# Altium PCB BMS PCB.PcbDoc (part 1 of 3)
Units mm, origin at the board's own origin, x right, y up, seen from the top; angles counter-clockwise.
Board outline 105 x 42 mm, 6 copper layers (TOP, GND TOP, IN, GND IN, GND BOT, BOT), stack 1.517 mm thick; 241 components, 153 nets, 670 pads, 889 vias.
Unrouted connection lines stored in the file: 76.
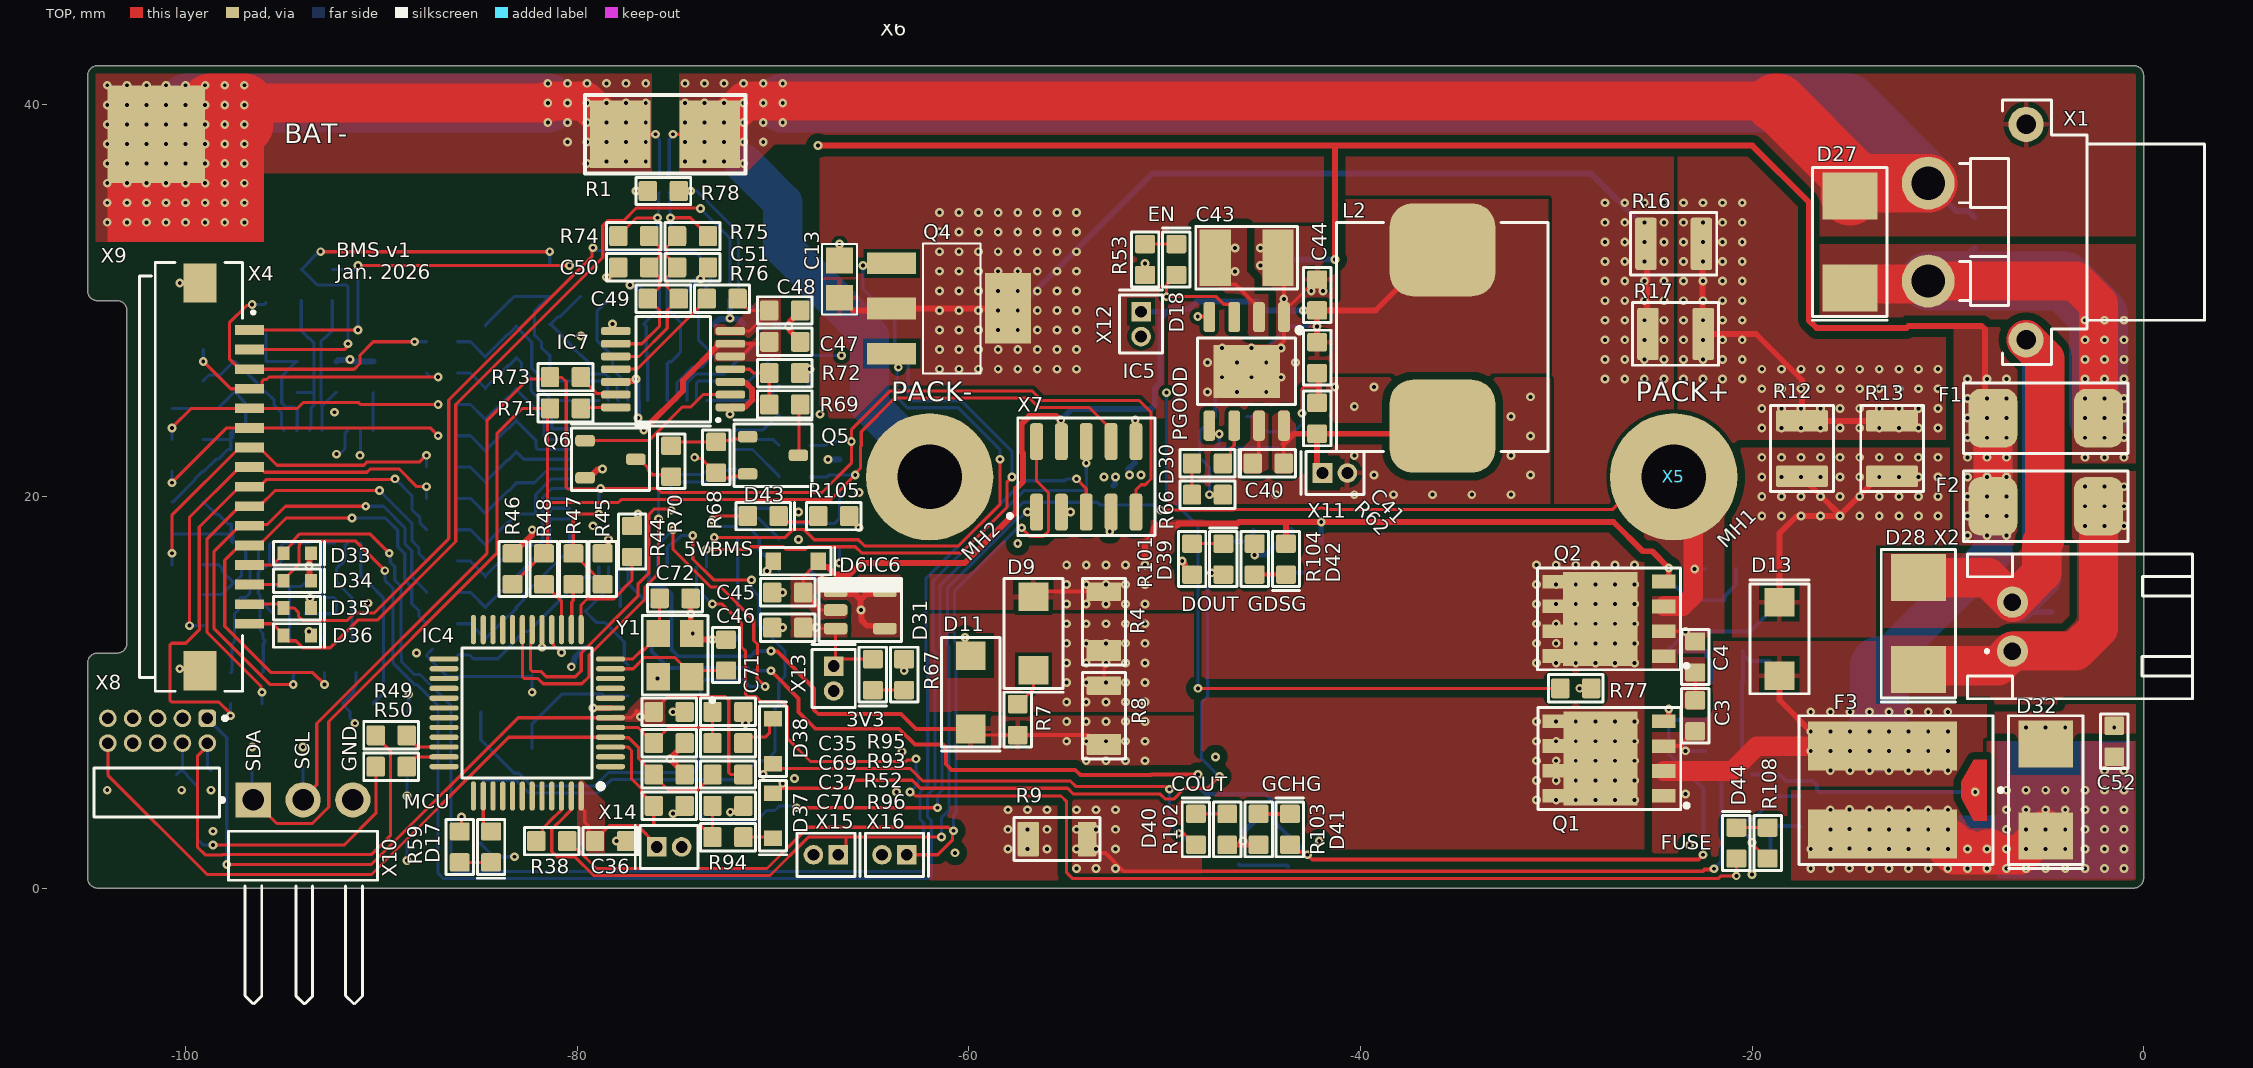
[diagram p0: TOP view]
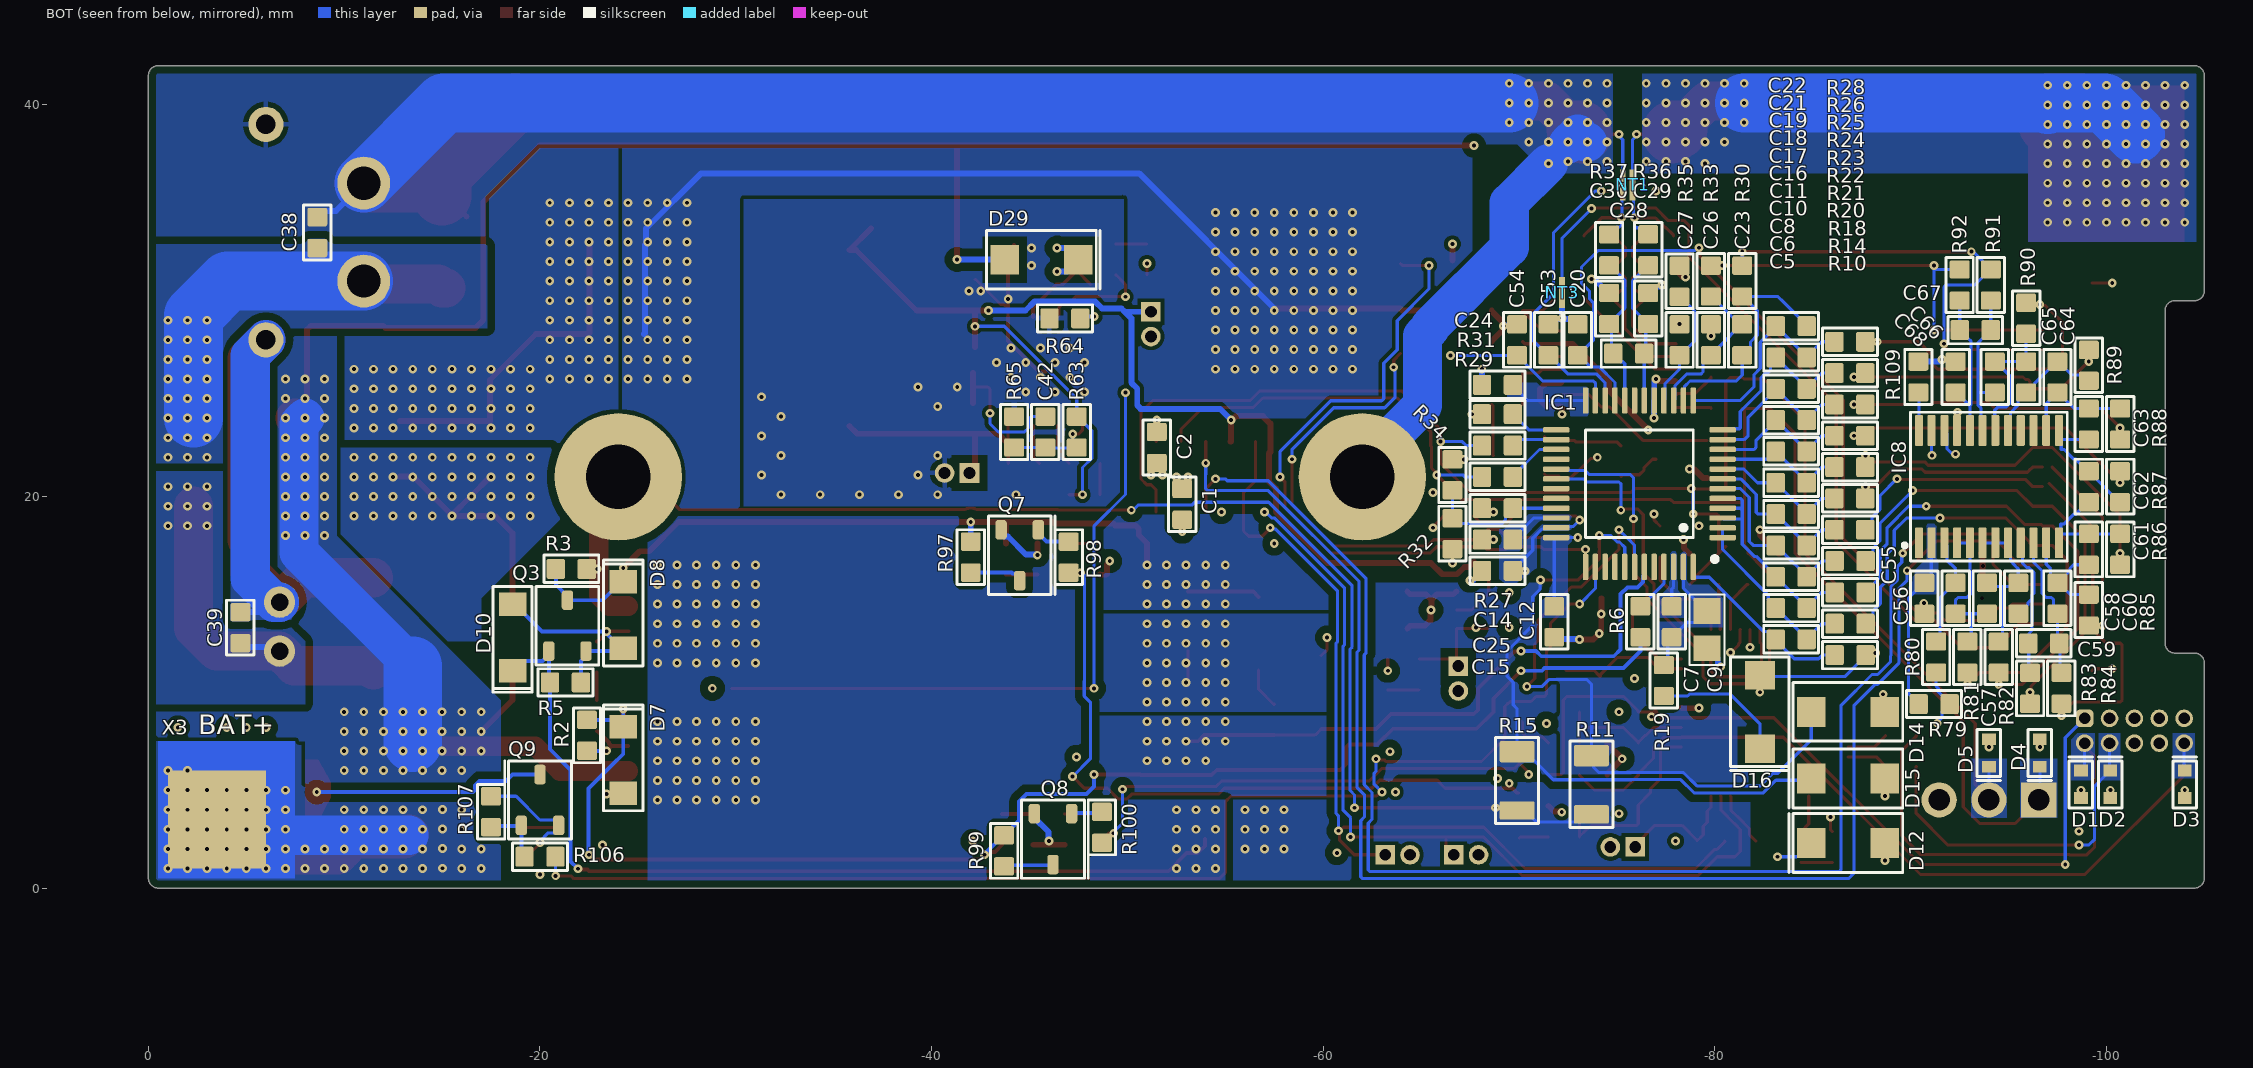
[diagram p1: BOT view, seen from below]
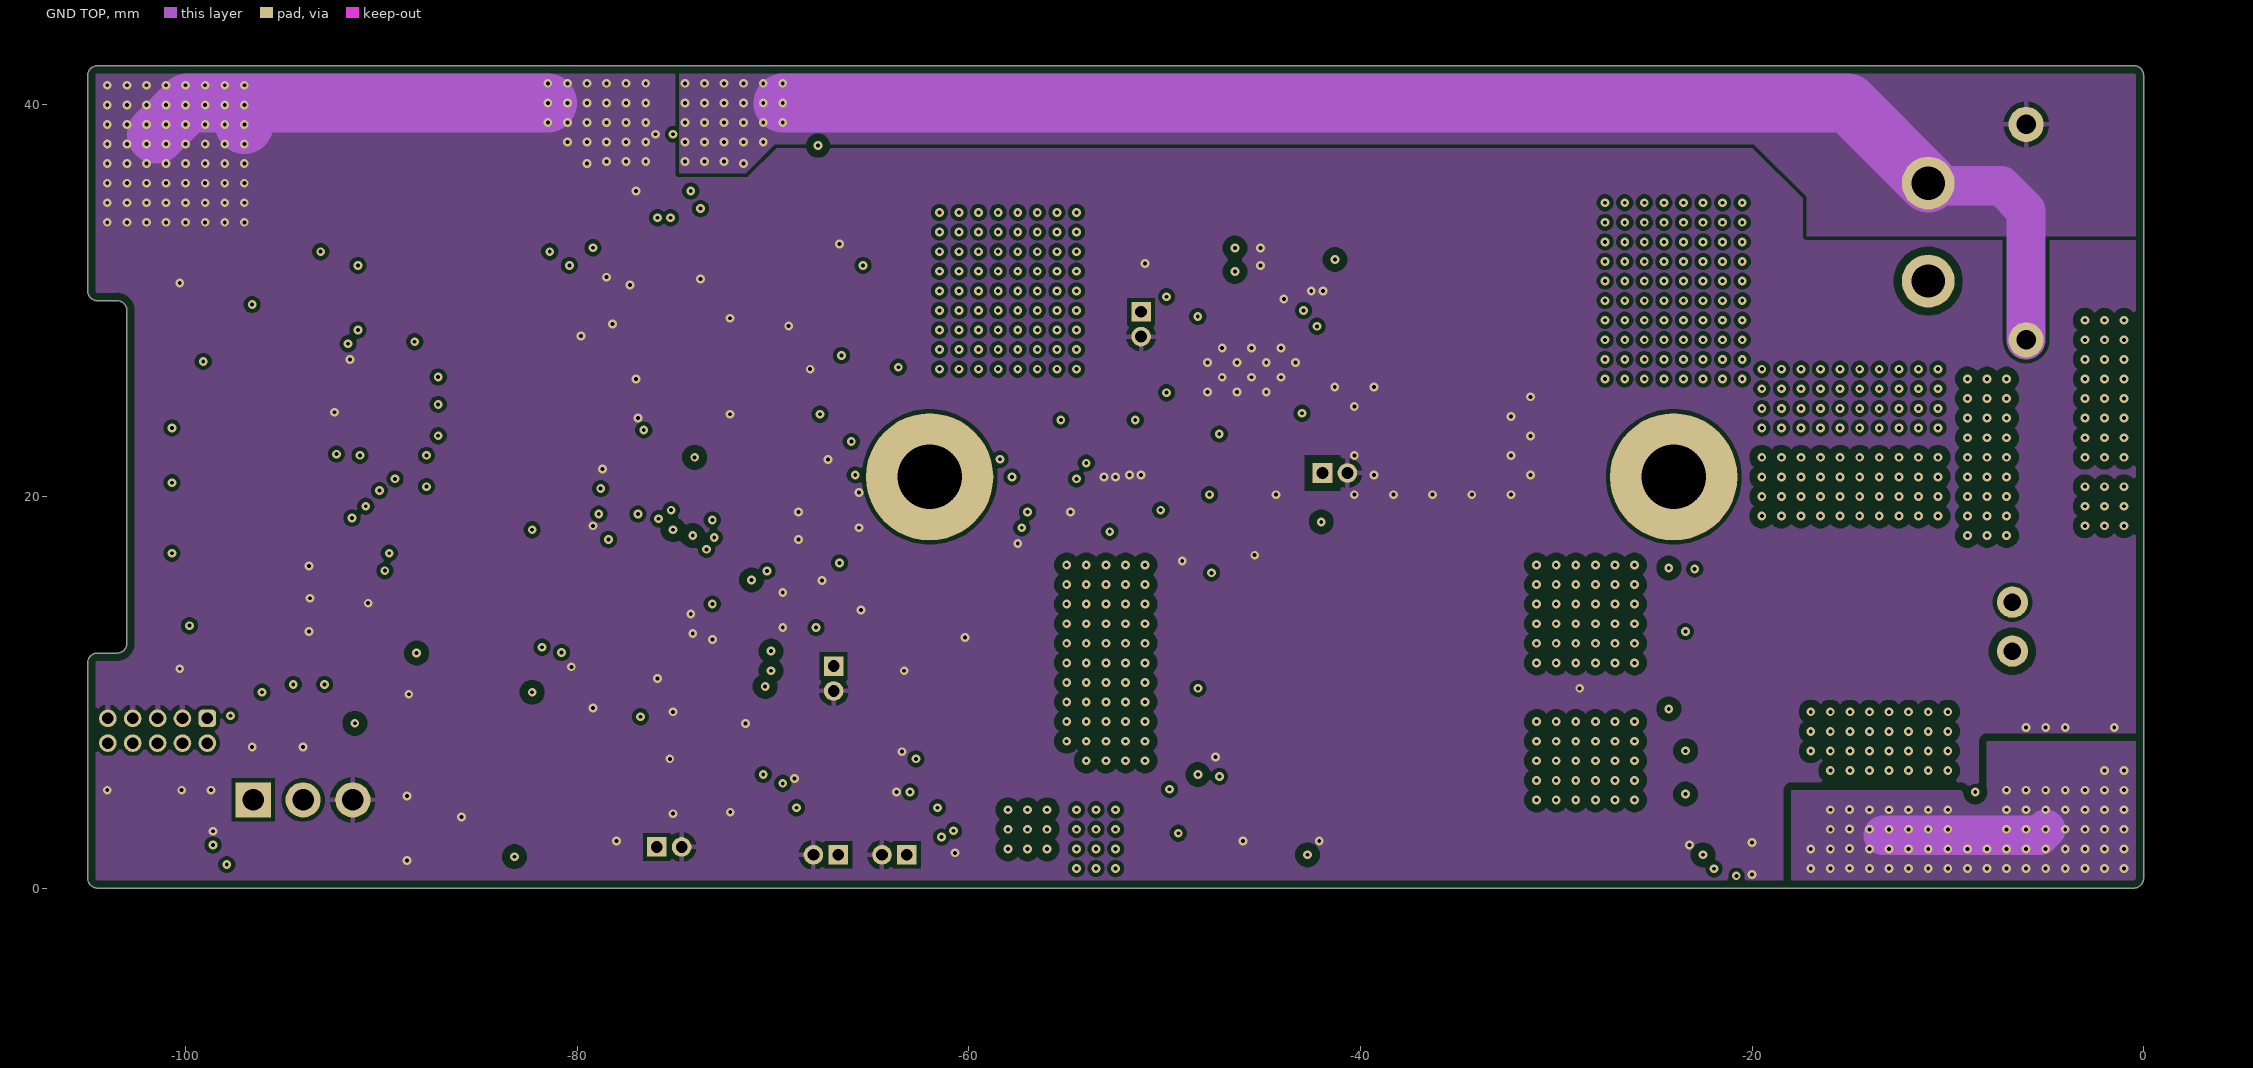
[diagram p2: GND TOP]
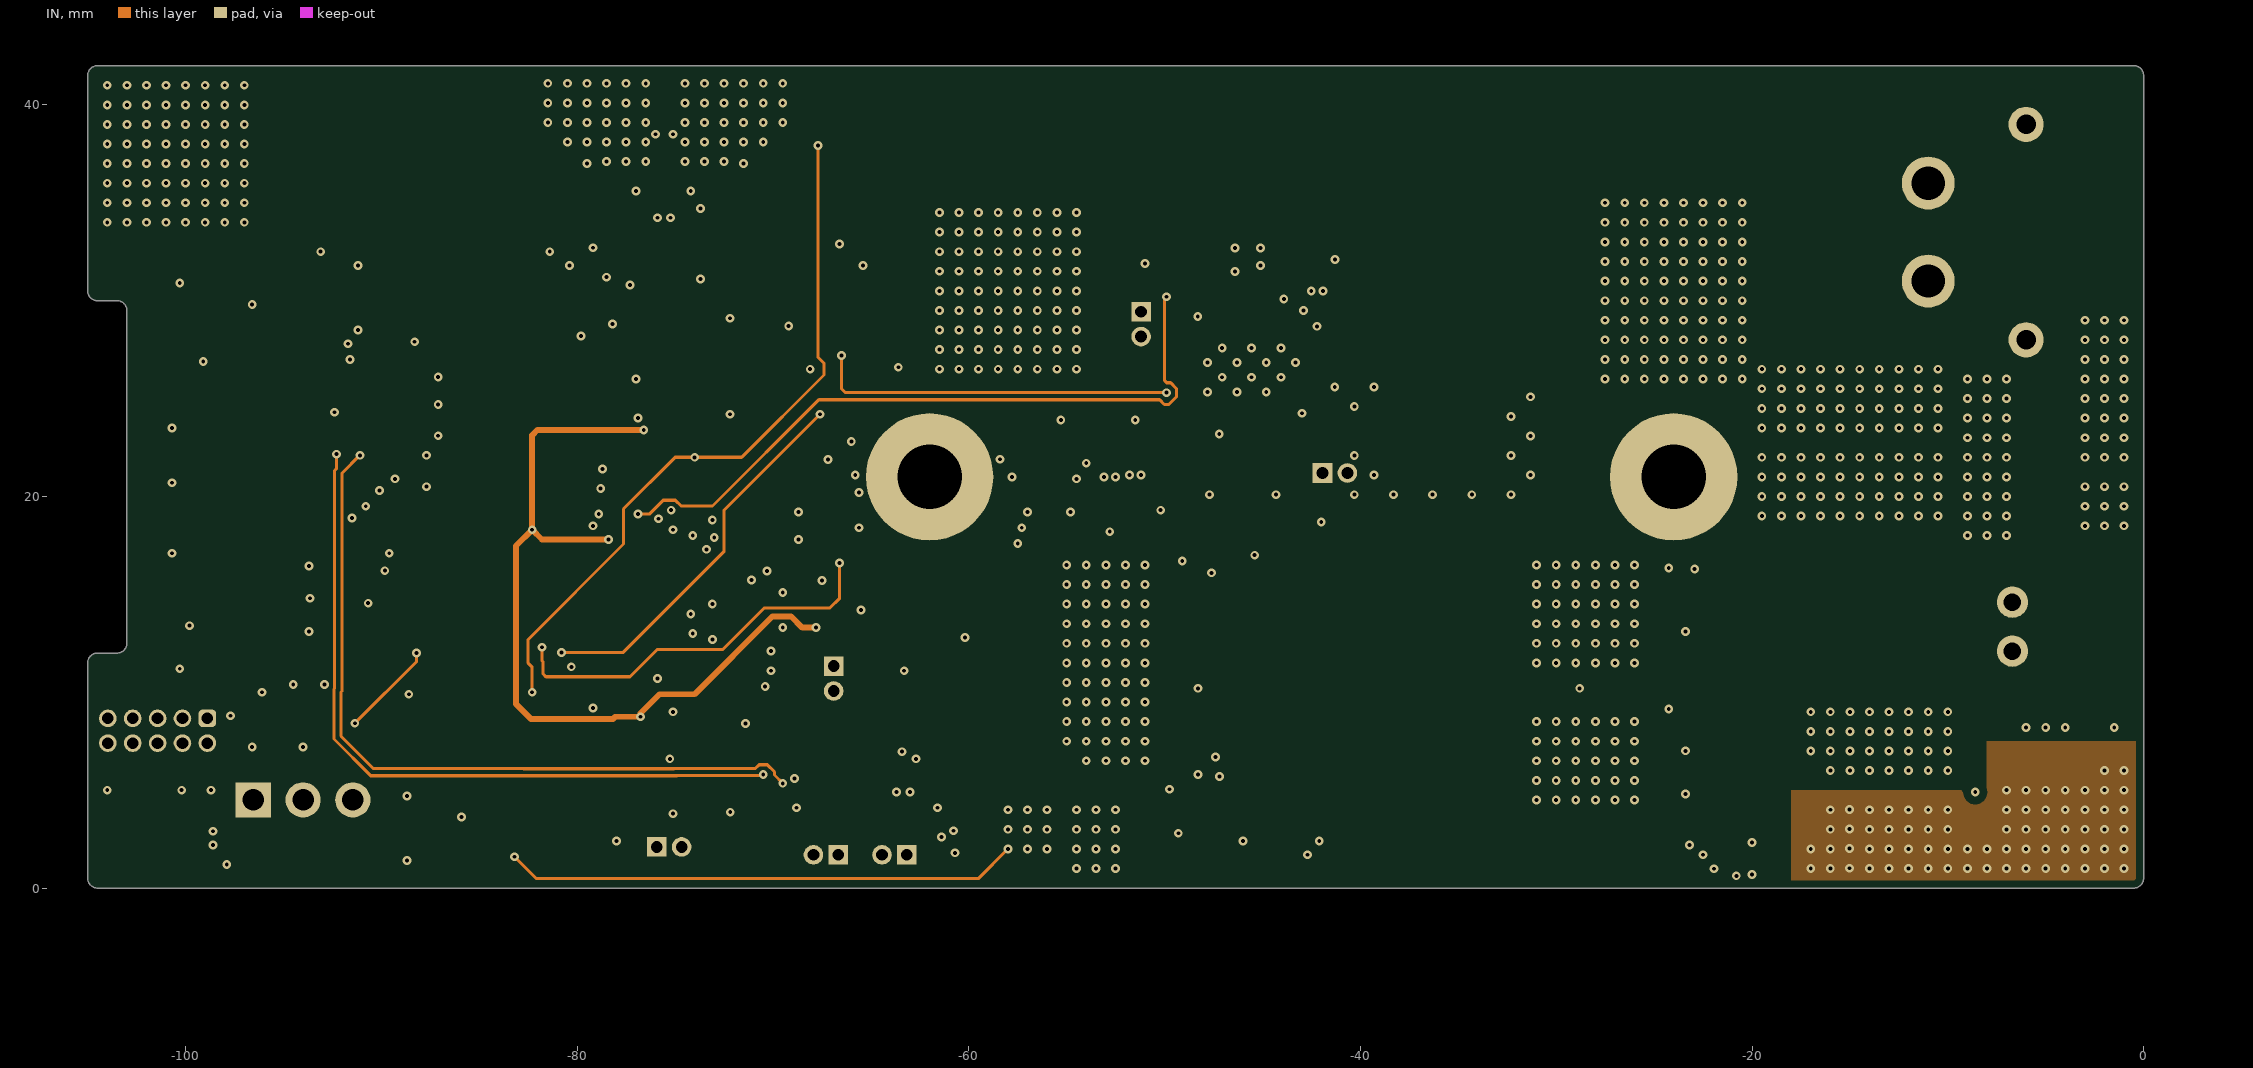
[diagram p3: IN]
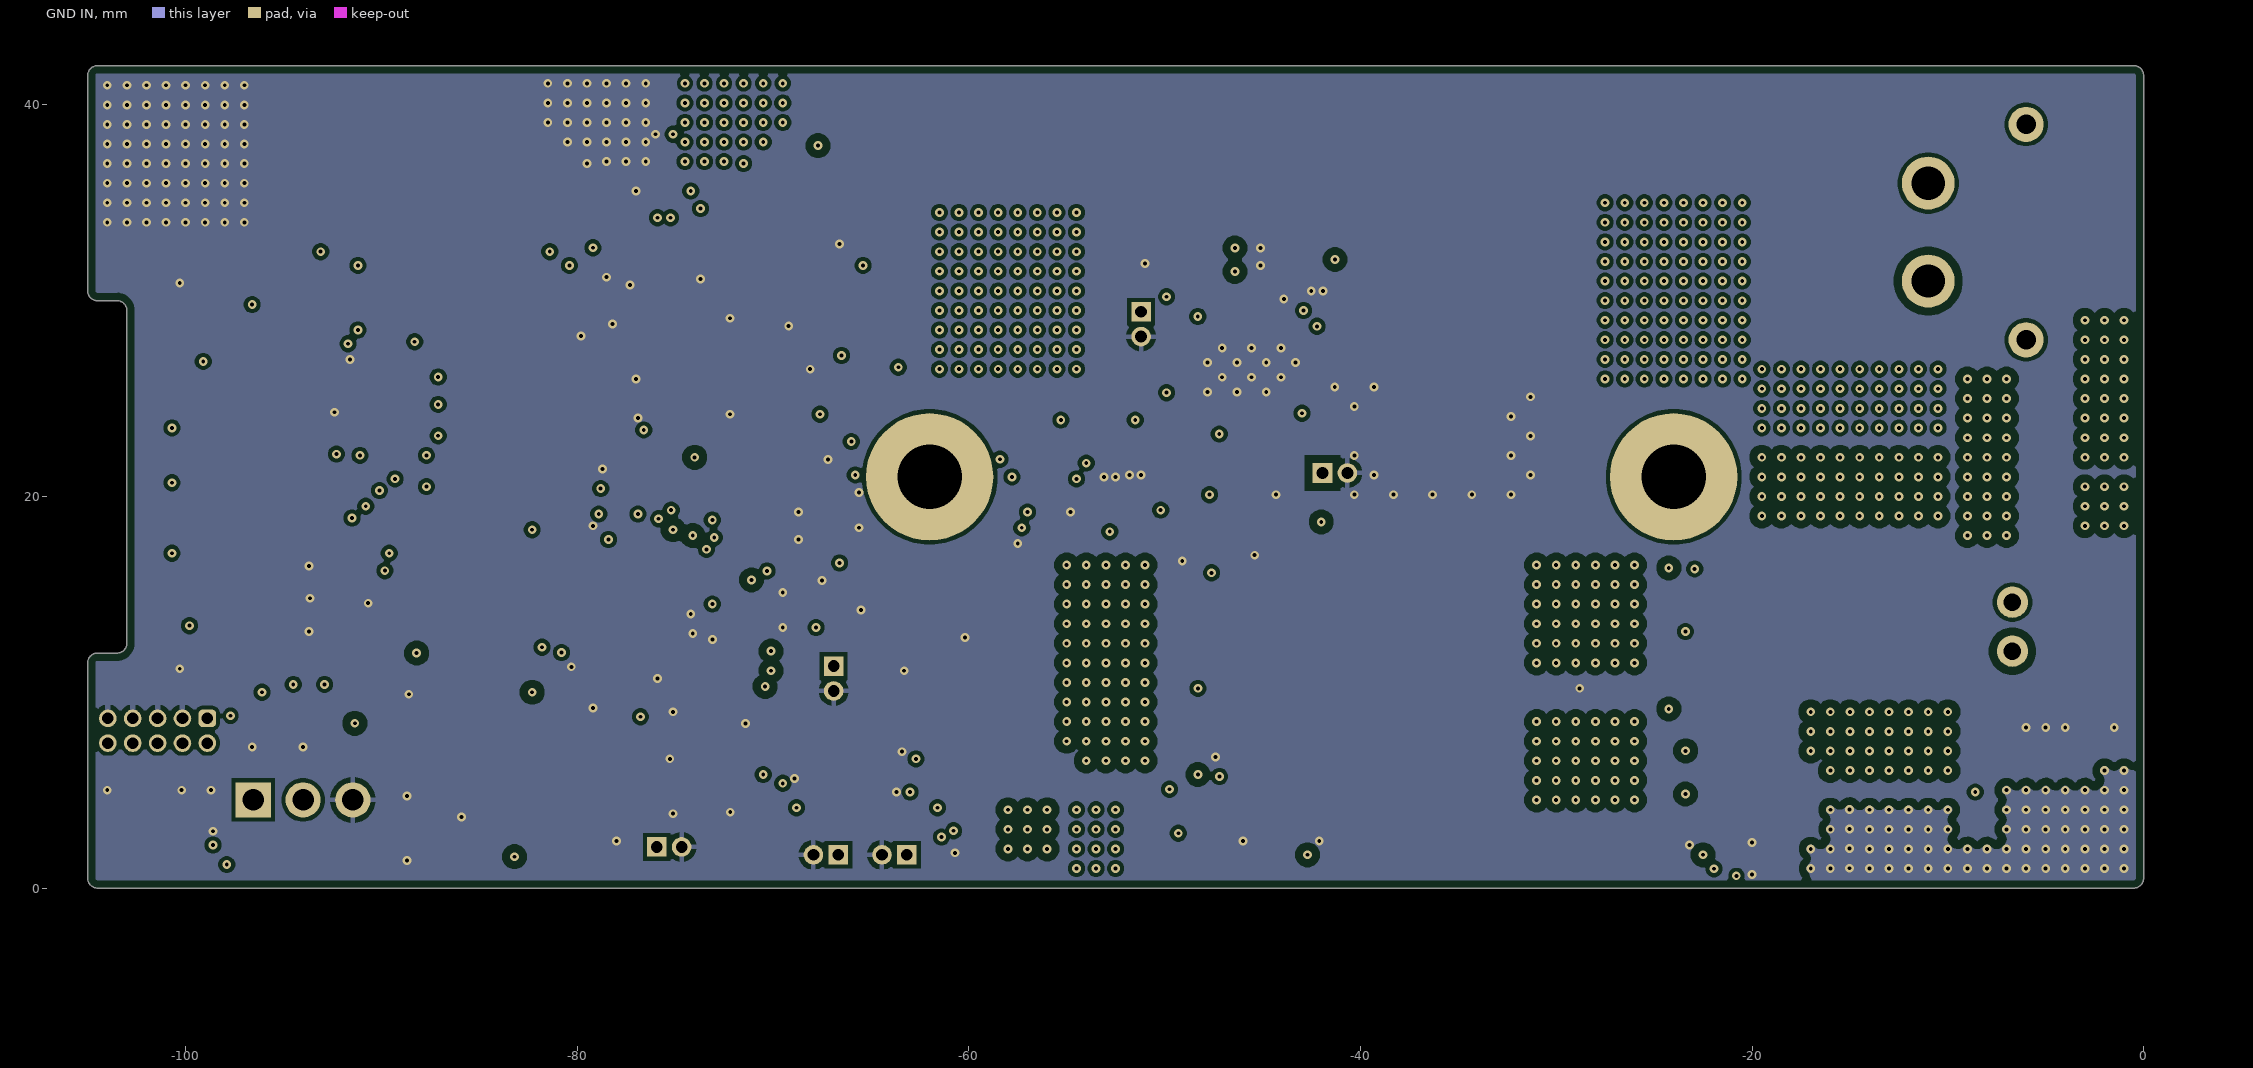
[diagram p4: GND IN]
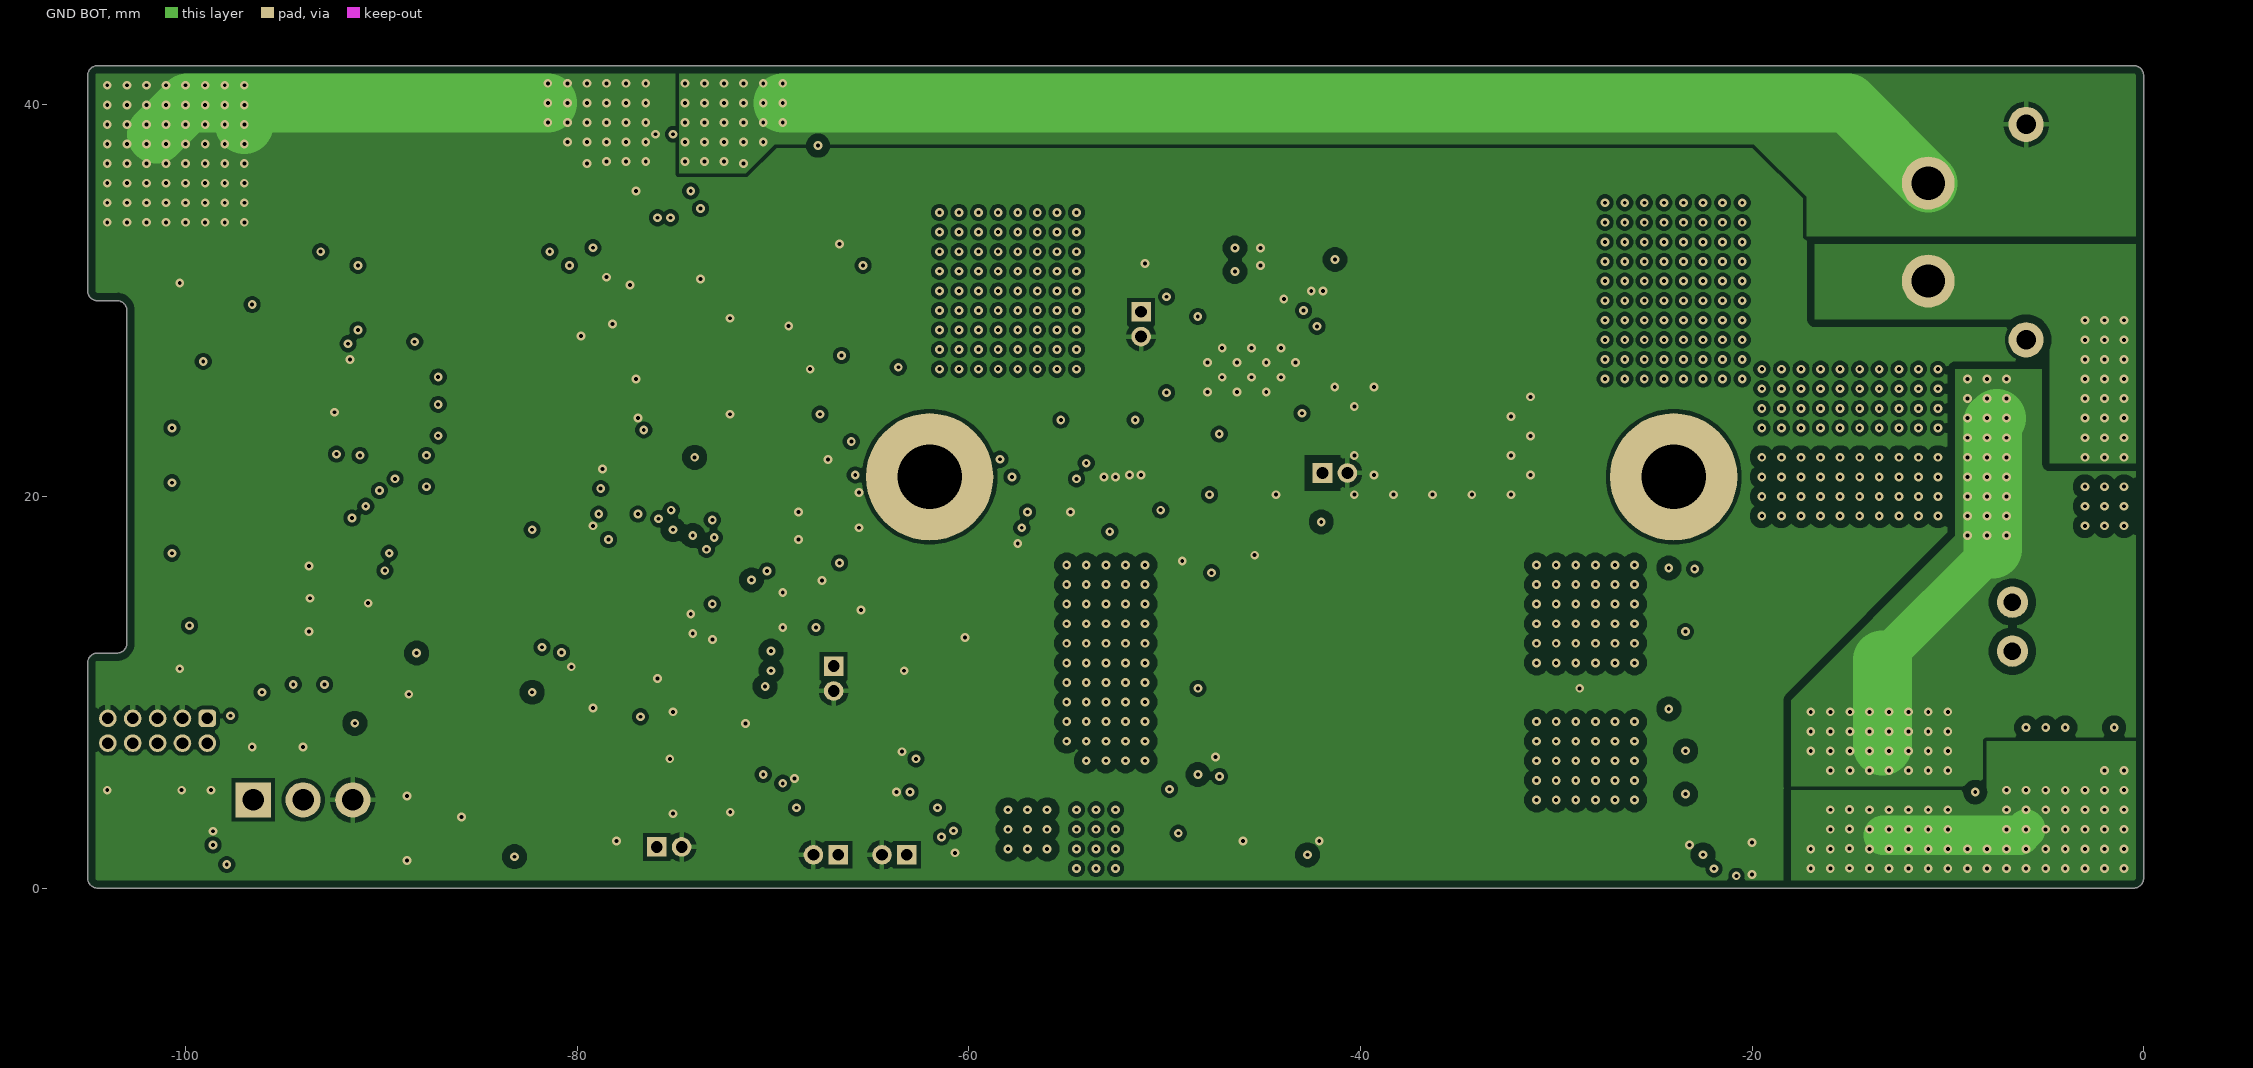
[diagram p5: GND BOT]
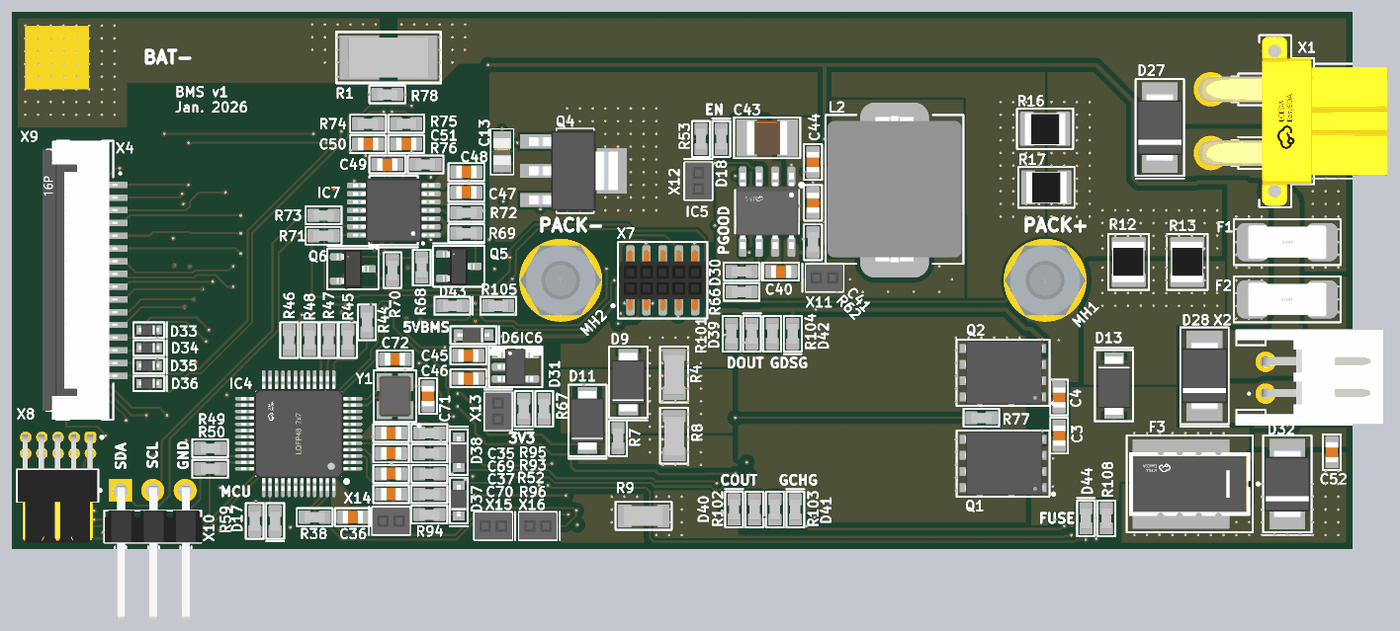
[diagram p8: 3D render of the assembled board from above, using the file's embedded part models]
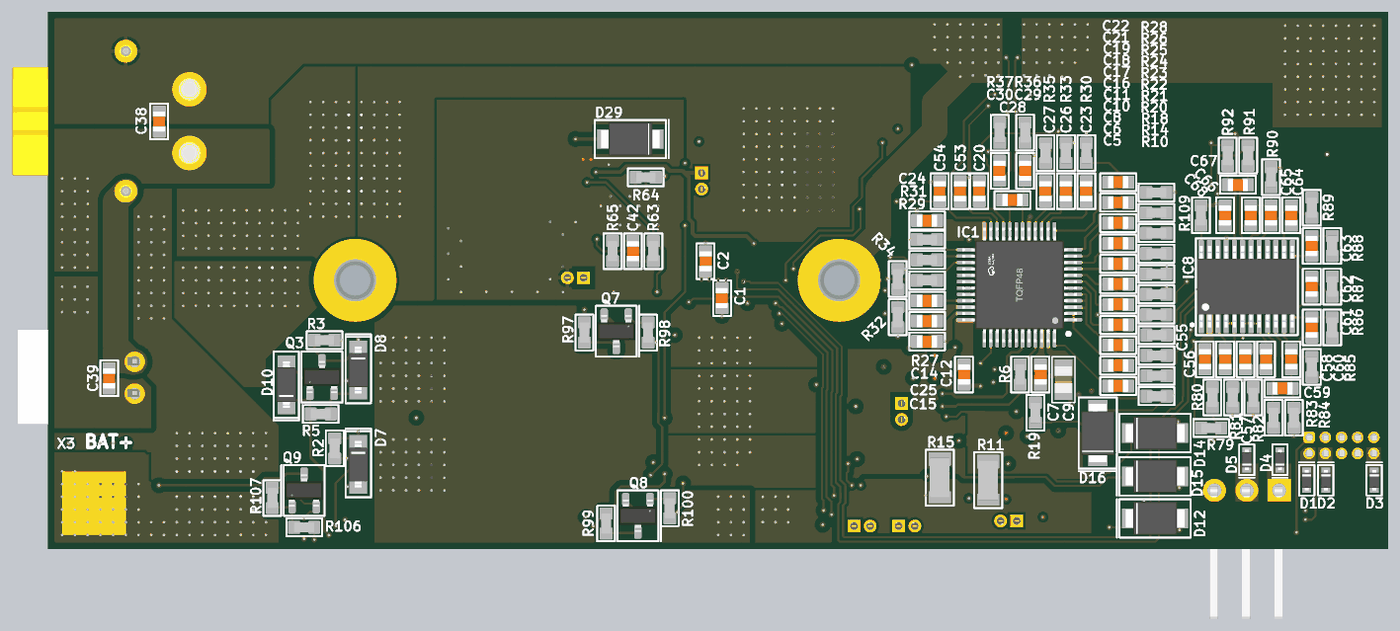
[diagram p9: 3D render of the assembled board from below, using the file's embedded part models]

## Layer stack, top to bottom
Top Solder: solder mask 0.0102, Solder Resist, Dk 3.5
TOP: signal copper 0.035
Dielectric 2: prepreg 0.0965, PP-013, Dk 4.3
GND TOP: signal copper 0.0175
Dielectric 4: core 0.5334, Core-037, Dk 4.8
IN: signal copper 0.0175
Dielectric 1: prepreg 0.1168, PP-016, Dk 4.4
GND IN: signal copper 0.0175
Dielectric 5: core 0.5334, Core-037, Dk 4.8
GND BOT: signal copper 0.0175
Dielectric 3: prepreg 0.0965, PP-013, Dk 4.3
BOT: signal copper 0.035
Bottom Solder: solder mask 0.0102, Solder Resist, Dk 3.5

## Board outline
-104.5,0 cw(c-104.5,0.5) -105,0.5 -105,11.5 cw(c-104.5,11.5) -104.5,12 -103.5,12 ccw(c-103.5,12.5) -103,12.5 -103,29.5 ccw(c-103.5,29.5) -103.5,30 -104.5,30 cw(c-104.5,30.5) -105,30.5 -105,41.5 cw(c-104.5,41.5) -104.5,42 -0.5,42 cw(c-0.5,41.5) 0,41.5 0,0.5 cw(c-0.5,0.5) -0.5,0

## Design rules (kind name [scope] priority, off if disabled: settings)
BoardOutlineClearance [All] p1: gap=0.4 ignorepadtopadclearanceinfootprint=FALSE
Clearance "VC9, VC8, VC7 vs OTHER" [InNetClass('VC9') OR InNetClass('VC8') OR InNetClass('VC7') vs Not InNetClass('VC9') OR Not InNetClass('VC8') OR Not InNetClass('VC7')] p1 off: gap=0.3 ignorepadtopadclearanceinfootprint=TRUE
Clearance "VC12, VC11, VC10 vs OTHER" [InNetClass('VC12') OR InNetClass('VC11') OR InNetClass('VC10') vs Not InNetClass('VC12') OR Not InNetClass('VC11') OR Not InNetClass('VC10')] p2 off: gap=0.4 ignorepadtopadclearanceinfootprint=TRUE
Clearance "PACK+_SW2 vs OTHER" [InNetClass('PACK+_SW2') vs Not InNetClass('PACK+_SW2')] p3: gap=0.4 ignorepadtopadclearanceinfootprint=TRUE
Clearance "PACK+ vs OTHER" [InNetClass('PACK+') vs Not InNetClass('PACK+')] p4: gap=0.4 ignorepadtopadclearanceinfootprint=TRUE
Clearance "BMS PP MID vs OTHER" [InNetClass('BMS PP MID') vs Not InNetClass('BMS PP MID')] p5: gap=0.4 ignorepadtopadclearanceinfootprint=TRUE
Clearance "BAT+ SW vs OTHER" [InNetClass('BAT+ SW') vs Not InNetClass('BAT+ SW')] p6: gap=0.4 ignorepadtopadclearanceinfootprint=TRUE
Clearance "BAT+ AUX FUSE vs OTHER" [InNetClass('BAT+ AUX FUSE') vs Not InNetClass('BAT+ AUX FUSE')] p7: gap=0.4 ignorepadtopadclearanceinfootprint=TRUE
Clearance "BAT+ FUSE vs OTHER" [InNetClass('BAT+ FUSE') vs Not InNetClass('BAT+ FUSE')] p8: gap=0.4 ignorepadtopadclearanceinfootprint=TRUE
Clearance "BAT+ vs OTHER" [InNetClass('BAT+') vs Not InNetClass('BAT+')] p9: gap=0.4 ignorepadtopadclearanceinfootprint=TRUE
Clearance "54Vac vs OTHER" [InNetClass('54Vac') vs Not InNetClass('54Vac')] p10: gap=0.4 ignorepadtopadclearanceinfootprint=TRUE
Clearance "48V_SW1 vs OTHER" [InNetClass('48V_SW1') vs not InNetClass('48V_SW1')] p11: gap=0.4 ignorepadtopadclearanceinfootprint=TRUE
Clearance "48V_PP vs OTHER" [InNetClass('48V_PP') vs Not InNetClass('48V_PP')] p12: gap=0.4 ignorepadtopadclearanceinfootprint=TRUE
Clearance "48V vs OTHER" [InNetClass('48V') vs Not InNetClass('48V')] p13: gap=0.4 ignorepadtopadclearanceinfootprint=TRUE
Clearance "CAN ISO vs OTHER" [InNetClass('CAN ISO') vs Not InNetClass('CAN ISO')] p14: gap=2 ignorepadtopadclearanceinfootprint=TRUE
Clearance Minimum [All] p15: gap=0.2 ignorepadtopadclearanceinfootprint=TRUE
ComponentClearance [All] p1: gap=0.5 collisioncheckmode=3 verticalgap=0.254 showdistances=FALSE
HoleSize [All] p1: absolutevalues=TRUE maxlimit=10 minlimit=0.2 maxpercent=80.000 minpercent=20.000
MinimumSolderMaskSliver [All] p1: minsoldermaskwidth=0.1
PolygonConnect [All] p1: thpad.connectstyle=Relief thpad.reliefconductorwidth=0.254 thpad.reliefentries=4 thpad.polygonreliefangle="90 Angle" thpad.airgapwidth=0.254 smdpad.connectstyle=Relief smdpad.reliefconductorwidth=0.254 smdpad.reliefentries=4 smdpad.polygonreliefangle="90 Angle" smdpad.airgapwidth=0.254 via.connectstyle=Direct via.reliefconductorwidth=0.254 via.reliefentries=4 via.polygonreliefangle="90 Angle" via.airgapwidth=0.254
RoutingVias [All] p1: holewidth=0.2 width=0.45 viastyle="Through Hole" minholewidth=0.2 minwidth=0.45 maxholewidth=0.3 maxwidth=0.6
SolderMaskExpansion Via [IsVia] p1: expansion=0.102 istentingtop=TRUE
SolderMaskExpansion General [All] p2: expansion=0 istentingtop=FALSE
Width [All] p1: maxlimit=5 minlimit=0.16 preferedwidth=0.16
27 further rules are at their usual default settings.

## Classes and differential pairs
component class "BQ7721606 PROTECTOR": C55 C56 C57 C58 C59 C60 C61 C62 C63 C64 C65 C66 C67 C68 D39 D40 IC8 R79 R80 R81 R82 R83 R84 R85 R86 R87 R88 R89 R90 R91 R92 R101 R102 R109
net class "BMS PP MID": NetQ1_D
net class VC12: C12 VC12
net class VC11: C11 VC11
net class VC10: C10 VC10
net class VC9: C9 VC9
net class VC8: C8 VC8
net class VC7: C7 VC7
net class VC6: C6 VC6
net class VC5: C5 VC5
net class VC4: C4 VC4
net class VC3: C3 VC3
net class VC2: C2 VC2
net class VC1: C1 VC1
net class BAT+: BAT BAT+ "BAT+ C" CHG CP1 G_CHG NC44 NetD13_K NetD16_K NetQ8_D VC13 "VIN 5V1"
net class "BAT+ SW": NetC40_1 "SW 5V1"
net class "BAT+ FUSE": NetC38_2
net class "BAT+ AUX FUSE": NetC39_2
component class "ESD system side": C38 C39 D27 D28
component class "ESD battery side": C52 D32 D33 D34 D35 D36
component class "BQ34Z100 FUEL GAUGE": C47 C48 C49 C50 C51 IC7 Q5 Q6 R68 R69 R70 R71 R72 R73 R74 R75 R76
component class "BAT+ to 5V1 STEP-DOWN": C40 C41 C42 C43 C44 D29 D30 IC5 L2 R62 R63 R64 R65 R66 X11 X12
component class "5V to 3V3 LDO": C45 C46 D31 IC6 R67
net class PACK+: DSG G_DSG LD NetD9_K NetD12_K NetQ7_D NetR4_1 PACK
component class MCU: C35 C36 C37 C69 C70 C71 C72 D17 D18 D37 D38 IC4 R38 R44 R45 R46 R47 R48 R49 R50 R52 R53 R59 R93 R94 R95 R96 X13 X14 X15 X16 Y1
component class "BQ76952 BMS": C3 C4 C5 C6 C7 C8 C9 C10 C11 C12 C13 C14 C15 C16 C17 C18 C19 C20 C21 C22 C23 C24 C25 C26 C27 C28 C29 C30 C53 C54 D7 D8 D9 D10 D11 D12 D13 D14 D15 D16 D41 D42 D43 D44 IC1 NT3 Q1 Q2 Q3 Q4 Q7 Q8 Q9 R2 R3 R4 R5 R6 R7 R8 R9 R10 R11 R12 R13 R14 R15 R16 R17 R18 R19 R20 R21 R22 R23 R24 R25 R26 R27 R28 R29 R30 R31 R32 R33 R34 R35 R36 R37 R77 R78 R97 R98 R99 R100 R103 R104 R105 R106 R107 R108
component class BMS: D6 NT1 NT2 R1
component class "BMS Arhitecture": C1 C2 D1 D2 D3 D4 D5 F1 F2 F3 MH1 MH2 X1 X2 X3 X4 X5 X6 X7 X8 X9 X10

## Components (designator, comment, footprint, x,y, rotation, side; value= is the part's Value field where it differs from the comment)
C1 "CL10B102KB8NNNC" "CAP 0603" -52.8,19.6 r270 bottom
C2 "CL10B102KB8NNNC" "CAP 0603" -51.5,22.5 r90 bottom
C3 "CC0603KRX7R0BB104" "CAP 0603" -22.9,8.8 r90 top
C4 "CC0603KRX7R0BB104" "CAP 0603" -22.9,11.8 r90 top
C5 "CL10B224KA8NNNC" "CAP 0603" -83.9,12.7 r0 bottom
C6 "CL10B224KA8NNNC" "CAP 0603" -83.9,14.3 r0 bottom
C7 "CL10B474KA8NNNC" "CAP 0603" -77.8,13.6 r90 bottom
C8 "CL10B224KA8NNNC" "CAP 0603" -83.9,15.9 r0 bottom
C9 "CC0805KKX7R0BB105" Cap_0805 -79.6,13.2 r90 bottom
C10 "CL10B224KA8NNNC" "CAP 0603" -83.9,17.5 r0 bottom
C11 "CL10B224KA8NNNC" "CAP 0603" -83.9,19.1 r0 bottom
C12 "CL10B223KB8NNNC" "CAP 0603" -71.8,13.6 r90 bottom
C13 "CC0805KKX7R0BB105" Cap_0805 -66.6,31.1 r270 top
C14 "CL10A106MA8NRNC" "CAP 0603" -68.9,17.8 r180 bottom
C15 "CL10A106MA8NRNC" "CAP 0603" -68.9,16.2 r180 bottom
C16 "CL10B224KA8NNNC" "CAP 0603" -83.9,20.7 r0 bottom
C17 "CL10B224KA8NNNC" "CAP 0603" -83.9,22.3 r0 bottom
C18 "CL10B224KA8NNNC" "CAP 0603" -83.9,23.9 r0 bottom
C19 "CL10B224KA8NNNC" "CAP 0603" -83.9,25.5 r0 bottom
C20 "0603B222K500NT" "CAP 0603" -73,28 r270 bottom
C21 "CL10B224KA8NNNC" "CAP 0603" -83.9,27.1 r0 bottom
C22 "CL10B224KA8NNNC" "CAP 0603" -83.9,28.7 r0 bottom
C23 "CL10B224KA8NNNC" "CAP 0603" -81.4,28 r270 bottom
C24 "CL10A106MA8NRNC" "CAP 0603" -68.9,25.7 r180 bottom
C25 "CC0603KRX7R9BB104" "CAP 0603" -68.9,19.4 r180 bottom
C26 "CL10B224KA8NNNC" "CAP 0603" -79.8,28 r270 bottom
C27 "CL10B224KA8NNNC" "CAP 0603" -78.2,28 r270 bottom
C28 "CC0603KRX7R9BB104" "CAP 0603" -75.6,27.3 r0 bottom
C29 "CC0603KRX7R9BB104" "CAP 0603" -76.6,29.6 r90 bottom
C30 "CC0603KRX7R9BB104" "CAP 0603" -74.6,29.6 r270 bottom
C35 "CGA0603X5R226M100JT" "CAP 0603" -75.3,9 r180 top
C36 "CL10B474KA8NNNC" "CAP 0603" -78.3,2.4 r180 top
C37 "0603B103K500NT" "CAP 0603" -75.3,5.8 r180 top
C38 "CC0603JRNPO0BN101" "CAP 0603" -8.625,33.475 r270 bottom
C39 "CC0603JRNPO0BN101" "CAP 0603" -4.7,13.3 r270 bottom
C40 "0603B222K500NT" "CAP 0603" -44.71,21.69 r0 top
C41 "0603B222K500NT" "CAP 0603" -42.21,27.09 r90 top
C42 "CC0603JRNPO9BN510" "CAP 0603" -45.81,23.29 r90 bottom
C43 "HMK325C7475KN-TE" CAP_1210 -45.81,32.19 r180 top
C44 "CGA0603X5R226M100JT" "CAP 0603" -42.21,30.29 r270 top
C45 "CC0603KRX7R0BB473" "CAP 0603" -69.245,15.1 r0 top
C46 "CL10A105KB8NNNC" "CAP 0603" -69.245,13.3 r0 top
C47 "CC0603KRX7R9BB104" "CAP 0603" -69.4,27.9 r180 top
C48 "CL10A105KB8NNNC" "CAP 0603" -69.4,29.5 r180 top
C49 "CC0603KRX7R9BB104" "CAP 0603" -75.6,30.1 r0 top
C50 "CC0603KRX7R9BB104" "CAP 0603" -77.11,31.7 r180 top
C51 "CC0603KRX7R9BB104" "CAP 0603" -74.11,31.7 r180 top
C52 "CC0603JRNPO0BN101" "CAP 0603" -1.5,7.5 r270 top
C53 "0603B222K500NT" "CAP 0603" -71.5,28 r270 bottom
C54 "0603B222K500NT" "CAP 0603" -69.9,28 r270 bottom
C55 "CC0603KRX7R0BB104" "CAP 0603" -90.7,14.8 r90 bottom
C56 "CC0603KRX7R0BB104" "CAP 0603" -92.3,14.8 r90 bottom
C57 "CC0603KRX7R0BB104" "CAP 0603" -93.9,14.8 r270 bottom
C58 "CC0603KRX7R0BB104" "CAP 0603" -95.5,14.8 r90 bottom
C59 "CC0603KRX7R0BB104" "CAP 0603" -96.8,12.5 r0 bottom
C60 "CC0603KRX7R0BB104" "CAP 0603" -97.5,14.8 r270 bottom
C61 "CC0603KRX7R0BB104" "CAP 0603" -99.1,17.3 r270 bottom
C62 "CC0603KRX7R0BB104" "CAP 0603" -99.1,20.5 r270 bottom
C63 "CC0603KRX7R0BB104" "CAP 0603" -99.1,23.7 r270 bottom
C64 "CC0603KRX7R0BB104" "CAP 0603" -97.5,26.1 r270 bottom
C65 "CC0603KRX7R0BB104" "CAP 0603" -95.9,26.1 r270 bottom
C66 "CC0603KRX7R0BB104" "CAP 0603" -94.3,26.1 r90 bottom
C67 "CC0603KRX7R0BB104" "CAP 0603" -93.3,28.5 r180 bottom
C68 "CC0603KRX7R0BB104" "CAP 0603" -92.3,26.1 r270 bottom
C69 "CL10B102KB8NNNC" "CAP 0603" -75.3,7.4 r180 top
C70 "CL10B102KB8NNNC" "CAP 0603" -75.3,4.2 r180 top
C71 "CL10C220JB8NNNC" "CAP 0603" -72.4,11.9 r270 top
C72 "CL10C220JB8NNNC" "CAP 0603" -75,14.8 r180 top
D1 "H3V3LD5B" SOD-523 -98.7,5.3 r270 bottom
D2 "H3V3LD5B" SOD-523 -100.2,5.3 r270 bottom
D3 "H3V3LD5B" SOD-523 -104,5.3 r270 bottom
D4 "H3V3LD5B" SOD-523 -96.6,6.9 r90 bottom
D5 "H3V3LD5B" SOD-523 -94,6.9 r90 bottom
D6 "1N5819WS" SOD-323 -68.845,16.7 r180 top
D7 "BZT52C16" SOD-123 -24.25,4.85 r90 bottom
D8 "BZT52C16" SOD-123 -24.25,12.25 r90 bottom
D9 "SS210F" SMAF -56.7,13 r90 top
D10 "BZT52C16" SOD-123 -18.6,14.5 r270 bottom
D11 "SS210F" SMAF -59.9,10 r90 top
D12 "SS210F" SMAF -86.8,2.3 r180 bottom
D13 "SS210F" SMAF -18.6,12.725 r270 top
D14 "SS210F" SMAF -86.8,9 r180 bottom
D15 "SS210F" SMAF -86.8,5.6 r180 bottom
D16 "SS210F" SMAF -82.3,9 r90 bottom
D17 "XL-1608UBC-04" DIODE_0603_BLUE -84.4,2.1 r90 top
D18 "XL-1608UOC-06" DIODE_0603_ORANGE -49.4,32.1 r270 top
D27 "SMBJ60A" DO-214AA -15,33 r90 top
D28 "SMBJ60A" DO-214AA -11.5,13.5 r90 top
D29 "SS210F" SMAF -45.61,32.09 r0 bottom
D30 "PSC-1608U52GC-G4" DIODE_0603_GREEN -47.81,21.69 r180 top
D31 "PSC-1608U52GC-G4" DIODE_0603_GREEN -64.9,10.9 r90 top
D32 "SMBJ60A" DO-214AA -5,5 r90 top
D33 "H3V3LD5B" SOD-523 -94.3,17.1 r180 top
D34 "H3V3LD5B" SOD-523 -94.3,15.7 r180 top
D35 "H3V3LD5B" SOD-523 -94.3,14.3 r180 top
D36 "H3V3LD5B" SOD-523 -94.3,12.9 r180 top
D37 "CUS08F30,H3F" SOD-323 -70,3.7 r90 top
D38 "CUS08F30,H3F" SOD-323 -70,7.5 r270 top
D39 "XL-1608SURC-06" DIODE_0603_RED -47,16.8 r270 top
D40 "XL-1608SURC-06" DIODE_0603_RED -48.4,3 r270 top
D41 "PSC-1608U52GC-G4" DIODE_0603_GREEN -43.6,3 r270 top
D42 "PSC-1608U52GC-G4" DIODE_0603_GREEN -43.8,16.8 r90 top
D43 "PSC-1608U52GC-G4" DIODE_0603_GREEN -70.5,19 r180 top
D44 "XL-1608SURC-06" DIODE_0603_RED -20.8,2.3 r270 top
F1 "STS2400" JFC2410-1500TS -5,24 r0 top
F2 "JFC2410-1500TS" JFC2410-1500TS -5,19.5 r0 top
F3 "WSFD4530" WSFD4530 -11,5 r180 top
IC1 "BQ76952PFBR" "TQFP-48 PFB" -80.4,17.9 r0 bottom
IC4 "MSPM0G3507SPTR" LQFP-48 -78.3,6.2 r180 top
IC5 "LM5163DDAR" ESOP-8 -45.81,26.39 r270 top
IC6 "TLV70433DBVR" SOT-23-5 -65.545,14.2 r0 top
IC7 "BQ34Z100PWR-R2" TSSOP-14 -75.1,26.5 r180 top
IC8 "BQ7721606PWR" TSSOP-24 -94,20.5 r90 bottom
L2 "SMMS1040-680MT" "IND 11.5x10mm" -35.81,28.09 r90 top
MH1 "M?" "M3 Plated" -24,21 r180 top locked
MH2 "M?" "M3 Plated" -62,21 r180 top locked
NT1 "NT" NETTIE_0.3MM -75.8,35.9 r270 bottom net-tie
NT2 "NT" NETTIE_0.3MM -75.3,35.9 r270 bottom net-tie
NT3 "NT" NETTIE_0.3MM -72.2,30.4 r270 bottom net-tie
Q1 "Pd = 290 mW" PDFN5*6-8L -27.74,6.615 r90 top
Q2 "Pd = 290mW" PDFN5*6-8L -27.75,13.75 r90 top
Q3 "2N7002" "SOT-23 GSD" -21.4,13.4 r180 bottom
Q4 "Pd = 600 mW" "SOT-223 NPN" -58,29.6 r180 top
Q5 "PJM10H01PSA" "SOT-23 GSD" -70,22.1 r270 top
Q6 "BSS123" "SOT-23 GSD" -78.3,21.9 r270 top
Q7 "BSS123" "SOT-23 GSD" -44.5,17 r0 bottom
Q8 "BSS123" "SOT-23 GSD" -46.2,2.5 r0 bottom
Q9 "5N10-MS" "SOT-23 GSD" -20,4.5 r180 bottom
R1 "Pd = 1 W" "2512 Shunt" -77.8,38.5 r0 top
R2 "0603WAF1005T5E" RES_0603 -22.4,7.8 r90 bottom
R3 "0603WAF1005T5E" RES_0603 -21.6,16.3 r180 bottom
R4 "Pd = 150 mW" RES_1206 -53.1,13.6 r90 top
R5 "0603WAF1005T5E" RES_0603 -21.3,10.5 r180 bottom
R6 "0603WAF1002T5E" RES_0603 -76.2,13.6 r270 bottom
R7 "0603WAF5101T5E" RES_0603 -57.5,8.6 r90 top
R8 "Pd = 150 mW" RES_1206 -53.1,8.8 r90 top
R9 "Pd = 300 mW" RES_1206 -55.5,2.5 r0 top
R10 "0603WAF220JT5E" RES_0603 -86.91,11.9 r0 bottom
R11 "Pd = 300 mW" RES_1206 -73.7,5.3 r270 bottom
R12 "Pd = 400 mW" RES_1210 -17.448,22.444 r270 top
R13 "Pd = 400 mW" RES_1210 -12.848,22.443 r270 top
R14 "0603WAF220JT5E" RES_0603 -86.91,13.5 r0 bottom
R15 "Pd = 300 mW" RES_1206 -69.9,5.5 r270 bottom
R16 "Pd = 400 mW" RES_1210 -24,32.9 r0 top
R17 "Pd = 400 mW" RES_1210 -23.9,28.3 r0 top
R18 "0603WAF220JT5E" RES_0603 -86.91,15.1 r0 bottom
R19 "0603WAF1000T5E" RES_0603 -77.4,10.6 r90 bottom
R20 "0603WAF220JT5E" RES_0603 -86.91,16.7 r0 bottom
R21 "0603WAF220JT5E" RES_0603 -86.9,18.3 r0 bottom
R22 "0603WAF220JT5E" RES_0603 -86.9,19.9 r0 bottom
R23 "0603WAF220JT5E" RES_0603 -86.9,21.5 r0 bottom
R24 "0603WAF220JT5E" RES_0603 -86.9,23.1 r0 bottom
R25 "0603WAF220JT5E" RES_0603 -86.9,24.7 r0 bottom
R26 "0603WAF220JT5E" RES_0603 -86.9,26.3 r0 bottom
R27 "0603WAF220JT5E" RES_0603 -68.9,21 r0 bottom
R28 "0603WAF220JT5E" RES_0603 -86.9,27.9 r0 bottom
R29 "0603WAF220JT5E" RES_0603 -68.9,22.6 r0 bottom
R30 "0603WAF220JT5E" RES_0603 -81.4,31 r270 bottom
R31 "0603WAF220JT5E" RES_0603 -68.9,24.2 r0 bottom
R32 "0603WAF1000T5E" RES_0603 -66.6,18.1 r270 bottom
R33 "0603WAF220JT5E" RES_0603 -79.8,31 r270 bottom
R34 "0603WAF1002T5E" RES_0603 -66.6,21.1 r270 bottom
R35 "0603WAF220JT5E" RES_0603 -78.2,30.99 r270 bottom
R36 "0603WAF1000T5E" RES_0603 -76.6,32.6 r270 bottom
R37 "0603WAF1000T5E" RES_0603 -74.6,32.59 r270 bottom
R38 "0603WAF220JT5E" RES_0603 -81.3,2.4 r0 top
R44 "0603WAF220JT5E" RES_0603 -77.2,17.7 r270 top
R45 "0603WAF1002T5E" RES_0603 -78.7,16.3 r90 top
R46 "0603WAF1002T5E" RES_0603 -83.3,16.3 r90 top
R47 "0603WAF220JT5E" RES_0603 -80.2,16.3 r270 top
R48 "0603WAF220JT5E" RES_0603 -81.7,16.3 r270 top
R49 "0603WAF220JT5E" RES_0603 -89.5,7.8 r180 top
R50 "0603WAF220JT5E" RES_0603 -89.5,6.2 r180 top
R52 "0603WAF4702T5E" RES_0603 -72.3,5.8 r0 top
R53 "0603WAF5101T5E" RES_0603 -51,32.1 r270 top
R59 "0603WAF5101T5E" RES_0603 -86,2.1 r90 top
R62 "0603WAF3163T5E" RES_0603 -42.21,23.99 r90 top
R63 "0603WAF3303T5E" RES_0603 -47.41,23.29 r90 bottom
R64 "0603WAF4222T5E" RES_0603 -46.81,29.09 r180 bottom
R65 "RT0603DRE07101KL" RES_0603 -44.21,23.29 r270 bottom
R66 "0603WAF1002T5E" RES_0603 -47.81,20.09 r0 top
R67 "0603WAF1002T5E" RES_0603 -63.3,10.9 r90 top
R68 "0603WAF1004T5E" RES_0603 -72.9,22 r270 top
R69 "AC0603FR-07953KL" RES_0603 -69.4,24.7 r0 top
R70 "0603WAF3304T5E" RES_0603 -75.2,21.8 r90 top
R71 "0603WAF220JT5E" RES_0603 -80.6,24.5 r180 top
R72 "RT0603BRD0716KL" RES_0603 -69.4,26.3 r180 top
R73 "0603WAF220JT5E" RES_0603 -80.6,26.1 r180 top
R74 "0603WAF1000T5E" RES_0603 -77.11,33.3 r0 top
R75 "0603WAF1000T5E" RES_0603 -74.11,33.3 r180 top
R76 "NCP18XH103F03RB" RES_0603 -72.6,30.1 r0 top
R77 "NCP18XH103F03RB" RES_0603 -29,10.2 r180 top
R78 "NCP18XH103F03RB" RES_0603 -75.6,35.6 r0 top
R79 "0603WAF4700T5E" RES_0603 -91.2,9.4 r0 bottom
R80 "0603WAF1001T5E" RES_0603 -91.3,11.8 r90 bottom
R81 "0603WAF1001T5E" RES_0603 -92.9,11.8 r90 bottom
R82 "0603WAF1001T5E" RES_0603 -94.5,11.8 r90 bottom
R83 "0603WAF1001T5E" RES_0603 -96.1,10.2 r90 bottom
R84 "0603WAF1001T5E" RES_0603 -97.7,10.2 r90 bottom
R85 "0603WAF1001T5E" RES_0603 -99.1,14.2 r90 bottom
R86 "0603WAF1001T5E" RES_0603 -100.7,17.3 r90 bottom
R87 "0603WAF1001T5E" RES_0603 -100.7,20.5 r270 bottom
R88 "0603WAF1001T5E" RES_0603 -100.7,23.7 r90 bottom
R89 "0603WAF1001T5E" RES_0603 -99.1,26.7 r270 bottom
R90 "0603WAF1001T5E" RES_0603 -95.9,29.1 r270 bottom
R91 "0603WAF1001T5E" RES_0603 -94.1,30.8 r270 bottom
R92 "0603WAF1001T5E" RES_0603 -92.5,30.8 r270 bottom
R93 "0603WAF1002T5E" RES_0603 -72.3,7.4 r0 top
R94 "0603WAF1002T5E" RES_0603 -72.3,2.6 r0 top
R95 "0603WAF1002T5E" RES_0603 -72.3,9 r180 top
R96 "0603WAF1002T5E" RES_0603 -72.3,4.2 r180 top
R97 "0603WAF1002T5E" RES_0603 -42,16.9 r90 bottom
R98 "0603WAF1000T5E" RES_0603 -47,16.9 r90 bottom
R99 "0603WAF1002T5E" RES_0603 -43.7,1.9 r90 bottom
R100 "0603WAF1000T5E" RES_0603 -48.7,3.1 r90 bottom
R101 "0603WAF1002T5E" RES_0603 -48.6,16.8 r270 top
R102 "0603WAF1002T5E" RES_0603 -46.8,3 r270 top
R103 "0603WAF8662T5E" RES_0603 -45.2,3 r270 top
R104 "0603WAF8662T5E" RES_0603 -45.4,16.8 r90 top
R105 "0603WAF1002T5E" RES_0603 -66.9,19 r0 top
R106 "0603WAF1000T5E" RES_0603 -20,1.6 r180 bottom
R107 "0603WAF1002T5E" RES_0603 -17.5,3.9 r270 bottom
R108 "0603WAF1002T5E" RES_0603 -19.2,2.3 r270 top
R109 "NCP18XH103F03RB" RES_0603 -90.4,26.1 r270 bottom
X1 "XT30PW-F20.G.Y" XT30PW-F20.G.Y -8.5,33.5 r90 top locked
X2 "S2B-XH-A(LF)(SN)" S2B-XH-A(LF)(SN) -6.7,12.1 r270 top locked
X3 "Solder pad SMD 5x5mm" "Solder pad SMD 5x5mm" -3.5,3.5 r180 bottom locked
X4 "FPC-1.0FX-16PWCR-H20" FPC-1.0FX-16PWCR-H20 -98,21 r270 top
X5 "971060324" 971060324 -24,21 r180 top locked
X6 "971060324" 971060324 -62,21 r180 top locked
X7 "PM127-2-05-S-4.3" "Female header 2x5 1.27mm SMD Vertical" -54,21 r90 top locked
X8 "FTSH-105-01-L-D-RA-K" "JTAG Cortex connector THT Right-angle" -98.89,8.67 r270 top
X9 "Solder pad SMD 5x5mm" "Solder pad SMD 5x5mm" -101.5,38.5 r0 top locked
X10 "PZ254R-11-03P" "Pin header 1x3 2.54mmP THT Right-angle" -96.54,4.5 r0 top
X11 "HX PM1.27-1x2P ZC" "HX PM1.27-1x2P ZC" -41.3,21.2 r0 top
X12 "HX PM1.27-1x2P ZC" "HX PM1.27-1x2P ZC" -51.2,28.8 r270 top
X13 "HX PM1.27-1x2P ZC" "HX PM1.27-1x2P ZC" -66.9,10.7 r270 top
X14 "HX PM1.27-1x2P ZC" "HX PM1.27-1x2P ZC" -75.3,2.1 r0 top
X15 "HX PM1.27-1x2P ZC" "HX PM1.27-1x2P ZC" -67.3,1.7 r180 top
X16 "HX PM1.27-1x2P ZC" "HX PM1.27-1x2P ZC" -63.8,1.7 r180 top
Y1 "S3240000121040" S3240000121040 -75,11.9 r90 top

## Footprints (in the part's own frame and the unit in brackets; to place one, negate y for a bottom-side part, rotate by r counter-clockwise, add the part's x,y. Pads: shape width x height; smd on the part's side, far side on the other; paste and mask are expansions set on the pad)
"2512 Shunt" [mm] "2512 Shunt resistor"
  rect 3.1x3.456 smd: 1(0,0) 2(4.572,0)
  silkscreen extent -1.8,-2 6.4,2, body extent -0.87,-1.57 5.47,1.57, height 0.75
971060324 [mm] "Standoff M3x6x6 Mech Male-Female"
  body extent -3.18,-2.75 3.18,2.75, height 6.01
"CAP 0603" [mm] "CAP 0603"
  rrect20% 0.94x1.02 smd: 1(-0.79,0) 2(0.79,0)
  silkscreen extent -1.4,-0.7 1.4,0.7, body extent -0.8,-0.5 0.8,0.47, height 0.81
Cap_0805 [mm]
  rect 1.312x1.396 smd: 1(-0.948,0) 2(0.948,0)
  silkscreen extent -1.8,-0.9 1.8,0.9, body extent -1.05,-0.67 1.05,0.67, height 1.35
CAP_1210 [mm] "Cap SMD 1210"
  rect 1.6x2.904 smd: 1(-1.6,0) 2(1.6,0)
  silkscreen extent -2.6,-1.6 2.6,1.6, body extent -1.6,-1.35 1.6,1.35, height 2.51
DIODE_0603_BLUE [mm]
  rrect20% 0.94x1.02 smd: A(0.79,0) K(-0.79,0)
  silkscreen extent -1.6,-0.7 1.4,0.7, body extent -0.8,-0.4 0.8,0.4, height 0.46
DIODE_0603_GREEN [mm] "LED Diode 0603 Green"
  rrect20% 0.94x1.02 smd: A(0.79,0) K(-0.79,0)
  silkscreen extent -1.6,-0.7 1.4,0.7, body extent -0.8,-0.4 0.8,0.4, height 0.46
DIODE_0603_ORANGE [mm] "RES 0603"
  rrect20% 0.94x1.02 smd: A(0.79,0) K(-0.79,0)
  silkscreen extent -1.6,-0.7 1.4,0.7, body extent -0.8,-0.4 0.8,0.4, height 0.46
DIODE_0603_RED [mm]
  rrect20% 0.94x1.02 smd: A(0.79,0) K(-0.79,0)
  silkscreen extent -1.6,-0.7 1.4,0.7, body extent -0.8,-0.4 0.8,0.4, height 0.46
DO-214AA [mm] "Diode package"
  rect 2.4x2.8 smd: A(2.35,0) K(-2.35,0)
  silkscreen extent -4,-1.9 3.8,1.9, body extent -2.67,-1.81 2.68,1.81, height 2.65
ESOP-8 [mm] "SOIC-8 Exposed pad package"
  rrect50% 1.55x0.6 smd: 1(-2.772,1.905) 2(-2.772,0.635) 3(-2.772,-0.635) 4(-2.772,-1.905) 5(2.772,-1.905) 6(2.772,-0.635) 7(2.772,0.635) 8(2.772,1.905)
  rect 2.71x3.4 smd: 9(0,0)
  silkscreen extent -2.11,-2.5 1.7,2.71, body extent -3.07,-2.44 2.93,2.46, height 1.71
"Female header 2x5 1.27mm SMD Vertical" [mm] "Female header 2x5 1.27mm SMD Vertical"
  rrect50% 1.9x0.66 smd: 1(-1.8,2.54) 2(1.8,2.54) 3(-1.8,1.27) 4(1.8,1.27) 5(-1.8,0) 6(1.8,0) 7(-1.8,-1.27) 8(1.8,-1.27) 9(-1.8,-2.54) 10(1.8,-2.54)
  silkscreen extent -3,-3.5 3,4, body extent -2.4,-3.37 2.4,3.38, height 4.51
FPC-1.0FX-16PWCR-H20 [mm] "FPC connector 16p 1.0mmP"
  rect 0.5x1.5 smd: 1(-7.5,1.263) 2(-6.5,1.263) 3(-5.5,1.263) 4(-4.5,1.263) 5(-3.5,1.263) 6(-2.5,1.263) 7(-1.5,1.263) 8(-0.5,1.263) 9(0.5,1.263) 10(1.5,1.263) 11(2.5,1.263) 12(3.5,1.263) 13(4.5,1.263) 14(5.5,1.263) 15(6.5,1.263) 16(7.5,1.263)
  rect 2x1.7 smd: CASE(-9.9,-1.263) CASE(9.9,-1.263)
  silkscreen extent -10.95,-4.35 10.95,1.46, body extent -10.96,-4.65 10.96,1.3, height 2.01
"HX PM1.27-1x2P ZC" [mm] "Female header 1x2 1.27mm THT Vertical"
  rect 1x1 hole 0.6: 1(-0.635,0)
  round 1 hole 0.6: 2(0.635,0)
  silkscreen extent -1.74,-1.1 1.48,1.1, body extent -1.48,-1.05 1.48,1.05, height 4.31
"IND 11.5x10mm" [mm] "SMD Power inductor"
  rrect50% 4.75x5.4 smd: 1(-4.5,0) 2(4.5,0)
  silkscreen extent -5.8,-5.4 5.9,5.4, body extent -5.68,-5.25 5.82,5.25, height 4.14
JFC2410-1500TS [mm] "Fuse SMD 2410"
  rrect50% 2.5x3 smd: 1(-2.7,0) 2(2.7,0)
  silkscreen extent -4.2,-1.8 4.2,1.8, body extent -3.1,-1.35 3.1,1.35, height 2.71
"JTAG Cortex connector THT Right-angle" [mm]
  rrect50% 0.9x0.9 hole 0.6: 1(0,0)
  round 0.9 hole 0.6: 2(1.27,0) 3(0,-1.27) 4(1.27,-1.27) 5(0,-2.54) 6(1.27,-2.54) 7(0,-3.81) 8(1.27,-3.81) 9(0,-5.08) 10(1.27,-5.08)
  silkscreen extent -0.1,-5.78 5.05,1, body extent -0.17,-5.72 8.28,0.56, height 5.09
LQFP-48 [mm] "LQFP-48"
  oval 1.5x0.27 smd mask+0: 1(0,0) 2(0,-0.5) 3(0,-1) 4(0,-1.5) 5(0,-2) 6(0,-2.5) 7(0,-3) 8(0,-3.5) 9(0,-4) 10(0,-4.5) 11(0,-5) 12(0,-5.5) 25(8.5,-5.5) 26(8.5,-5) 27(8.5,-4.5) 28(8.5,-4) 29(8.5,-3.5) 30(8.5,-3) 31(8.5,-2.5) 32(8.5,-2) 33(8.5,-1.5) 34(8.5,-1) 35(8.5,-0.5) 36(8.5,0)
  oval 0.27x1.5 smd mask+0: 13(1.5,-7) 14(2,-7) 15(2.5,-7) 16(3,-7) 17(3.5,-7) 18(4,-7) 19(4.5,-7) 20(5,-7) 21(5.5,-7) 22(6,-7) 23(6.5,-7) 24(7,-7) 37(7,1.5) 38(6.5,1.5) 39(6,1.5) 40(5.5,1.5) 41(5,1.5) 42(4.5,1.5) 43(4,1.5) 44(3.5,1.5) 45(3,1.5) 46(2.5,1.5) 47(2,1.5) 48(1.5,1.5)
  silkscreen extent 0.49,-6.05 7.59,1.01, body extent -0.25,-7.25 8.75,1.75, height 1.41
"M3 Plated" [mm] "M3 hole"
  round 6.5 hole 3.3: 1(0,0)
NETTIE_0.3MM [mm] "NetTie 0.3mm"
  rect 0.81x0.3 smd paste-5 mask+0.102: 1(-0.4,0) 2(0.375,0)
PDFN5*6-8L [mm] "Mosfet package"
  rect 0.7x1.2 smd: D(-1.9,2.36) D(-0.63,2.36) D(0.64,2.36) D(1.9,2.36) G(1.905,-3.24) S(-1.905,-3.24) S(-0.635,-3.24) S(0.635,-3.24)
  rect 4.8x3.8 smd: D(0,0)
  silkscreen extent -2.6,-4.5 2.6,3.2, body extent -2.6,-3.6 2.6,2.55, height 0.93
"Pin header 1x3 2.54mmP THT Right-angle" [mm] "Pin header 1x3 2.54mmP THT Right-angle"
  rect 1.8x1.8 hole 1.1: 1(0,0)
  round 1.8 hole 1.1: 2(2.54,0) 3(5.08,0)
  silkscreen extent -1.7,-10.4 6.34,0.1, body extent -1.22,-10.1 6.42,0.3, height 2.51
RES_0603 [mm] "RES 0603"
  rrect20% 0.94x1.02 smd: 1(-0.79,0) 2(0.79,0)
  silkscreen extent -1.4,-0.7 1.4,0.7, body extent -0.8,-0.4 0.8,0.4, height 0.46
RES_1206 [mm]
  rrect14% 1.09x1.77 smd: 1(-1.465,0)
  rrect14% 0.94x1.77 smd: 2(1.54,0)
  silkscreen extent -2.2,-1.1 2.2,1.1, body extent -1.55,-0.77 1.55,0.78, height 0.56
RES_1210 [mm] "RESISTOR 1210"
  rrect20% 1.1x2.67 smd: 1(-1.415,0) 2(1.415,0)
  silkscreen extent -2.2,-1.6 2.2,1.6, body extent -1.6,-1.27 1.6,1.23, height 0.56
S2B-XH-A(LF)(SN) [mm] "JST XH 1x2 2.50mmP THT Right-angle"
  round 1.6 hole 0.9: 1(0,0) 2(-2.5,0)
  silkscreen extent -4.97,-2.3 2.43,9.2, body extent -5,-2.3 2.4,9.2, height 5.91
S3240000121040 [mm] "Crystal oscillator"
  rect 1.4x1.2 smd: 1(-1.1,-0.85) 2(1.1,-0.85) 3(1.1,0.85) 4(-1.1,0.85)
  silkscreen extent -2.4,-2 2.03,1.68, body extent -1.6,-1.25 1.6,1.25, height 0.61
SMAF [mm] "DIODE SMAF"
  rect 1.46x1.53 smd: A(1.875,0) K(-1.875,0)
  silkscreen extent -3,-1.5 2.8,1.5, body extent -2.3,-1.3 2.3,1.3, height 1.11
SOD-123 [mm] "Diode FP"
  rect 1.2x1.4 smd: A(0,0) K(3.4,0)
  silkscreen extent -0.9,-1 4.5,1, body extent -0.13,-0.77 3.52,0.77, height 1.44
SOD-323 [mm] "Diode package"
  rect 0.8x0.9 smd: A(1.15,0) K(-1.15,0)
  silkscreen extent -2,-0.7 1.8,0.7, body extent -1.25,-0.63 1.25,0.63, height 1.11
SOD-523 [mm] "SOD-523 diode"
  rect 0.6x0.7 smd: A(0.7,0) K(-0.7,0)
  silkscreen extent -1.4,-0.6 1.2,0.6, body extent -0.8,-0.4 0.8,0.4, height 0.71
"Solder pad SMD 5x5mm" [mm]
  rect 5x5 smd paste-5: 1(0,0)
"SOT-23 GSD" [mm] "Nmos SOT23 Gate Source Drain"
  rrect50% 0.583x1 smd: D(0,1.3) G(-0.95,-1.3) S(0.95,-1.3)
  silkscreen extent -1.8,-2 1.6,2, body extent -1.51,-1.26 1.51,1.26, height 1.12
SOT-23-5 [mm] "IC package"
  rrect50% 1.21x0.59 smd: 1(-1.255,0.95) 2(-1.255,0) 3(-1.255,-0.95) 4(1.255,-0.95) 6(1.255,0.95)
  silkscreen extent -2.1,-1.6 2.1,1.6, body extent -1.4,-1.45 1.4,1.45, height 1.45
"SOT-223 NPN" [mm] "SOT-223 NPN pinout"
  rect 2.5x1.1 smd: B(5.94,-2.3) C(5.94,0) E(5.94,2.3)
  rect 2.34x3.6 smd: C(0,0)
  silkscreen extent 1.4,-3.33 4.34,3.33, body extent -0.5,-3.15 6.5,3.15, height 1.71
"TQFP-48 PFB" [mm] "IC package"
  rrect50% 1.35x0.28 smd mask+0.05: 1(0,0) 2(0,-0.5) 3(0,-1) 4(0,-1.5) 5(0,-2) 6(0,-2.5) 7(0,-3) 8(0,-3.5) 9(0,-4) 10(0,-4.5) 11(0,-5) 12(0,-5.5) 25(8.5,-5.5) 26(8.5,-5) 27(8.5,-4.5) 28(8.5,-4) 29(8.5,-3.5) 30(8.5,-3) 31(8.5,-2.5) 32(8.5,-2) 33(8.5,-1.5) 34(8.5,-1) 35(8.5,-0.5) 36(8.5,0)
  rrect50% 0.28x1.35 smd mask+0.05: 13(1.5,-7) 14(2,-7) 15(2.5,-7) 16(3,-7) 17(3.5,-7) 18(4,-7) 19(4.5,-7) 20(5,-7) 21(5.5,-7) 22(6,-7) 23(6.5,-7) 24(7,-7) 37(7,1.5) 38(6.5,1.5) 39(6,1.5) 40(5.5,1.5) 41(5,1.5) 42(4.5,1.5) 43(4,1.5) 44(3.5,1.5) 45(3,1.5) 46(2.5,1.5) 47(2,1.5) 48(1.5,1.5)
  silkscreen extent 0.3,-5.5 7,1.2, body extent -0.26,-7.25 8.75,1.77, height 1.3
TSSOP-14 [mm] "TSSOP-14"
  rrect50% 1.5x0.4 smd: 1(-2.925,1.95) 2(-2.925,1.3) 3(-2.925,0.65) 4(-2.925,0) 5(-2.925,-0.65) 6(-2.925,-1.3) 7(-2.925,-1.95) 8(2.925,-1.95) 9(2.925,-1.3) 10(2.925,-0.65) 11(2.925,0) 12(2.925,0.65) 13(2.925,1.3) 14(2.925,1.95)
  silkscreen extent -2.31,-2.7 1.9,2.9, body extent -3.2,-2.5 3.2,2.5, height 1.2
TSSOP-24 [mm] "IC"
  rrect25% 1.57x0.41 smd mask+0.05: 1(-2.87,3.575) 2(-2.87,2.925) 3(-2.87,2.275) 4(-2.87,1.625) 5(-2.87,0.975) 6(-2.87,0.325) 7(-2.87,-0.325) 8(-2.87,-0.975) 9(-2.87,-1.625) 10(-2.87,-2.275) 11(-2.87,-2.925) 12(-2.87,-3.575) 13(2.87,-3.575) 14(2.87,-2.925) 15(2.87,-2.275) 16(2.87,-1.625) 17(2.87,-0.975) 18(2.87,-0.325) 19(2.87,0.325) 20(2.87,0.975) 21(2.87,1.625) 22(2.87,2.275) 23(2.87,2.925) 24(2.87,3.575)
  silkscreen extent -3.8,-4 3.8,4.4, body extent -3.2,-3.9 3.2,3.9, height 1.2
WSFD4530 [mm] "Fuse"
  rect 7.6x2.5 smd: 1(2.335,2.25) 2(2.335,-2.25)
  round 0.26 smd: 3(-2.335,0)
  TOP region: -2.985,1.55 -2.335,1.55 -1.685,0.38 -1.685,-0.43 -2.335,-1.55 -2.985,-1.55 -2.985,1.55
  silkscreen extent -3.8,-3.8 6.6,3.8, body extent -3.1,-2.5 6.4,2.5, height 2.03
XT30PW-F20.G.Y [mm] "XT30 Female"
  round 2.7 hole 1.7 copper offset 0,0: +(-2.5,2.5) -(2.5,2.5)
  round 1.8 hole 1 copper offset 0,0: CASE(-5.5,-2.5) CASE(5.5,-2.5)
  silkscreen extent -6.75,-11.6 6.75,0.9, body extent -6.65,-11.4 6.65,3.49, height 5.21

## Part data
C1 C2 C69 C70: "Cap 1nF 50V 0603 X7R", Capacitance=1n, Case Code (Imperial)=0603, Manufacturer=Samsung, Supplier Part Number 1=?, Voltage Rating=50V
C3 C4 C55 C56 C57 C58 C59 C60 C61 C62 C63 C64 C65 C66 C67 C68: "Cap 100nF 100V 0603 X7R", Capacitance=100n, Case Code (Imperial)=0603, Manufacturer=YAGEO, Supplier Part Number 1=?, Voltage Rating=100V
C5 C6 C8 C10 C11 C16 C17 C18 C19 C21 C22 C23 C26 C27: "Cap 220nF 25V 0603 X7R", Capacitance=220n, Case Code (Imperial)=0603, Manufacturer=Samsung, Supplier Part Number 1=?, Voltage Rating=25V
C7 C36: "Cap 470nF 25V 0603 X7R", Capacitance=470n, Case Code (Imperial)=0603, Manufacturer=Samsung, Supplier Part Number 1=?, Voltage Rating=25V
C9 C13: "Cap 1uF 100V 0805 X7R", Capacitance=1u, Case Code (Imperial)=0805, Manufacturer=Yageo, Supplier Part Number 1=?, Voltage Rating=100V
C12: "Cap 22nF 50V 0603 X7R", Capacitance=22n, Case Code (Imperial)=0603, Manufacturer=Samsung, Supplier Part Number 1=?, Voltage Rating=50V
C14 C15 C24: "Cap 10uF 25V 0603 X5R", Capacitance=10u, Case Code (Imperial)=0603, Manufacturer=Samsung, Supplier Part Number 1=?, Voltage Rating=25V
C20 C40 C41 C53 C54: "Cap 2n2F 50V 0603 X7R", Capacitance=2n2, Case Code (Imperial)=0603, Manufacturer=FH, Supplier Part Number 1=?, Voltage Rating=50V
C25 C28 C29 C30 C47 C49 C50 C51: "Cap 100nF 50V 0603 X7R", Capacitance=100n, Case Code (Imperial)=0603, Manufacturer=Yageo, Supplier Part Number 1=?, Voltage Rating=50V
C35 C44: "Cap 22uF 10V 0603 X5R", Capacitance=22u, Case Code (Imperial)=0603, Manufacturer=HRE, Supplier Part Number 1=?, Voltage Rating=10V
C37: "Cap 10nF 50V 0603 X7R", Capacitance=10n, Case Code (Imperial)=0603, Manufacturer=FH, Supplier Part Number 1=?, Voltage Rating=50V
C38 C39 C52: "Cap 100pF 100V 0603 NP0", Capacitance=100p, Case Code (Imperial)=0603, Manufacturer=Yageo, Manufacturer Part Number=CC0603KRX7R9BB104, Supplier Part Number 1=?, Voltage Rating=100V
C42: "Cap 51pF 50V 0603 NP0", Capacitance=51p, Case Code (Imperial)=0603, Manufacturer=Yageo, Supplier Part Number 1=?, Voltage Rating=50V
C43: "Cap 4.7uF 100V 1210 X7R", Capacitance=4u7, Case Code (Imperial)=1210, Manufacturer="Taiyo Yuden", Supplier Part Number 1=?, Voltage Rating=100V
C45: "Cap 47nF 100V 0603 X7R", Capacitance=47n, Case Code (Imperial)=0603, Manufacturer=Yageo, Supplier Part Number 1=?, Voltage Rating=100V
C46 C48: "Cap 1uF 50V 0603 X5R", Capacitance=1u, Case Code (Imperial)=0603, Manufacturer=Samsung, Supplier Part Number 1=?, Voltage Rating=50V
C71 C72: "Cap 22pF 50V 0603 C0G", Capacitance=22p, Case Code (Imperial)=0603, Manufacturer=Samsung, Supplier Part Number 1=?, Voltage Rating=50V
D1 D2 D3 D4 D5 D33 D34 D35 D36: "ESD TVS 3.3Vrw 0.2uA 12.5pF", Manufacturer=hongjiacheng, Supplier Part Number 1=?
D6: "Schottky 40V 1A 600mVf SOD-323", Forward Current=1A, Manufacturer="Guangdong Hottech", Reverse Voltage=40V, Supplier Part Number 1=?
D7 D8 D10: "Zener 16V 500mW SOD-123", Manufacturer=TWGMC, Power Rating=500mW, Reverse Voltage=16V, Supplier Part Number 1=?
D9 D11 D12 D13 D14 D15 D16 D29: "Schottky 100V 2A 850mVf SMAF", Forward Current=2A, Manufacturer=GOODWORK, Reverse Voltage=100V, Supplier Part Number 1=?
D17: "LED Blue 0603 25mA", Manufacturer=Xinglight
D18: "LED Orange 0603 20mA", Manufacturer=XINGLIGHT
D27 D28 D32: "TVS ESD Zener UniD 60Vrw 1uA", Manufacturer="Shandong Jingdao Microelectronics", Reverse Voltage=60Vrw, Supplier Part Number 1=?
D30 D31 D41 D42 D43: "LED Green 0603 20mA", Manufacturer=HONGLITRONIC
D37 D38: "Schottky 30V 800mA 220mVf SOD-323", Forward Current=0.8A, Forward Voltage=220mVf, Manufacturer=Toshiba, Reverse Voltage=30V, Supplier Part Number 1=?
D39 D40 D44: "LED Red 0603 25mA", Manufacturer=Xinglight
F1: "Fuse SMD 63V 40A 2410", Hold Current=40A, Manufacturer=Reomax, Supplier Part Number 1=?, Voltage=63V
F2: "Fuse SMD 250V 5A 2410", Hold Current=5A, Manufacturer="JDT Fuse", Supplier Part Number 1=?, Voltage=250V
F3: "Fuse Trip SMD 80V 45A 120Abr", Hold Current=45A, Manufacturer="TLC Electronic", Supplier Part Number 1=?, Voltage=80V
IC1: "BMS IC 3~16s", Manufacturer="Texas Instruments", Supplier Part Number 1=BQ7695201PFBR
IC4: "MCU MSPM0G3507SPTR LQFP-48", Manufacturer="Texas Instruments"
IC5: "DCDC Step-down Converter 9~100Vin 0.5Aout", Manufacturer="Texas Instruments"
IC6: "LDO 24Vin 3.3Vout 150mA SOT-23-5", Manufacturer="Texas Instruments"
IC7: "Fuel gauge", Manufacturer="Texas Instruments"
IC8: "BMS Secondary protector IC 3~16s", Manufacturer="Texas Instruments"
L2: "Inductor 68uH 3.8A 220mR SMD 11.5x10mm", Inductance=68uH, Manufacturer=SXN, Resistance=220mR, Saturation current=3.8Asat, Supplier Part Number 1=?
MH1 MH2: library part "Mounting hole", "Generic mounting hole symbol"
NT1 NT2 NT3: library part NetTie, "Net Tie"
Q1 Q2: library part HYG053N10NS1C2, "Nmos 100V 95A 5.3mR PDFN5x6-8L", Manufacturer=HUAYI, Voltage=100V
Q3: "nMOS 60V 115mA SOT-23", Manufacturer="Jiangsu Changjing Electronics Technology Co., Ltd.", Voltage=60V
Q4: library part CZT5551, "NPN 160V 600mA SOT-223 1W", Current=600mA, Manufacturer=Jiangsu, Voltage=160V
Q5: "Pmos 100V 1A 650mR SOT-23", Manufacturer=PJSEMI, Voltage=100V
Q6 Q7 Q8: "Nmos 100V 170mA SOT-23", Manufacturer=hongjiacheng, Voltage=100V
Q9: "Nmos 100V 5A SOT-23", Manufacturer=MSKSEMI, Voltage=100V
R1: library part HoYLR2512E-3W-1mR-1%, "RES 1mR 2512 3W 1%", Case Code (Imperial)=2512, Manufacturer=Miliohm, Power Rating=3W, Resistance=1mR, Resistance Tolerance=1%, Supplier Part Number 1=?
R2 R3 R5: "Res 10M 0603 1% 100mW 75V", Case Code (Imperial)=0603, Manufacturer=Uni-Royal, Power Rating=100mW, Resistance=10M, Resistance Tolerance=1%, Supplier Part Number 1=?
R4 R8: library part HP06W2J0512T5E, "Res 5k1 1206 5% 500mW 200V", Case Code (Imperial)=1206, Manufacturer=Uni-Royal, Power Rating=500mW, Resistance=5k1, Resistance Tolerance=5%, Supplier Part Number 1=?
R6 R34 R45 R46 R66 R67 R93 R94 R95 R96 R97 R99 R101 R102 R105 R107 R108: "Res 10k 0603 1% 100mW 75V", Case Code (Imperial)=0603, Manufacturer=Uni-Royal, Power Rating=100mW, Resistance=10k, Resistance Tolerance=1%, Supplier Part Number 1=?
R7 R53 R59: "Res 5k1 0603 1% 100mW 75V", Case Code (Imperial)=0603, Manufacturer=Uni-Royal, Power Rating=100mW, Resistance=5k1, Resistance Tolerance=1%, Supplier Part Number 1=?
R9 R11 R15: library part 1206W4F1002T5E, "Res 10k 1206 1% 250mW 200V", Case Code (Imperial)=1206, Manufacturer=Uni-Royal, Power Rating=250mW, Resistance=10k, Resistance Tolerance=1%, Supplier Part Number 1=?
R10 R14 R18 R20 R21 R22 R23 R24 R25 R26 R27 R28 R29 R30 R31 R33 R35 R38 R44 R47 R48 R49 R50 R71 R73: "Res 22R 0603 1% 100mW 75V", Case Code (Imperial)=0603, Manufacturer=Uni-Royal, Power Rating=100mW, Resistance=22R, Resistance Tolerance=1%, Supplier Part Number 1=?
R12 R13 R16 R17: library part "FRC1210J821 TS", "Res 820R 1210 5% 500mW 200V", Case Code (Imperial)=1210, Manufacturer=FOJAN, Power Rating=500mW, Resistance=820R, Resistance Tolerance=5%, Supplier Part Number 1=?
R19 R32 R36 R37 R74 R75 R98 R100 R106: "Res 100R 0603 1% 100mW 75V", Case Code (Imperial)=0603, Manufacturer=Uni-Royal, Power Rating=100mW, Resistance=100R, Resistance Tolerance=1%, Supplier Part Number 1=?
R52: "Res 47k 0603 1% 100mW 75V", Case Code (Imperial)=0603, Manufacturer=Uni-Royal, Power Rating=100mW, Resistance=47k, Resistance Tolerance=1%, Supplier Part Number 1=?
R62: "Res 316k 0603 1% 100mW 75V", Case Code (Imperial)=0603, Manufacturer=Uni-Royal, Power Rating=100mW, Resistance=316k, Resistance Tolerance=1%, Supplier Part Number 1=?
R63: "Res 330k 0603 1% 100mW 75V", Case Code (Imperial)=0603, Manufacturer=Uni-Royal, Power Rating=100mW, Resistance=330k, Resistance Tolerance=1%, Supplier Part Number 1=?
R64: "Res 42k2 0603 1% 100mW 75V", Case Code (Imperial)=0603, Manufacturer=Uni-Royal, Power Rating=100mW, Resistance=42k2, Resistance Tolerance=1%, Supplier Part Number 1=?
R65: "Res 101k 0603 0.5% 100mW 75V", Case Code (Imperial)=0603, Manufacturer=YAGEO, Power Rating=100mW, Resistance=101k, Resistance Tolerance=0%5, Supplier Part Number 1=?
R68: "Res 1M 0603 1% 100mW 75V", Case Code (Imperial)=0603, Manufacturer=Uni-Royal, Power Rating=100mW, Resistance=1M, Resistance Tolerance=1%, Supplier Part Number 1=?
R69: "Res 953k 0603 1% 100mW 75V", Case Code (Imperial)=0603, Manufacturer=YAGEO, Power Rating=100mW, Resistance=953k, Resistance Tolerance=1%, Supplier Part Number 1=?
R70: "Res 3M3 0603 1% 100mW 75V", Case Code (Imperial)=0603, Manufacturer=Uni-Royal, Power Rating=100mW, Resistance=3M3, Resistance Tolerance=1%, Supplier Part Number 1=?
R72: "Res 16k 0603 0.1% 100mW 75V 25ppm", Case Code (Imperial)=0603, Manufacturer=YAGEO, Power Rating=100mW, Resistance=16k, Resistance Tolerance=0%1, Supplier Part Number 1=?
R76 R77 R78 R109: "NTC 10k 0603 1% 3455K", Case Code (Imperial)=0603, Manufacturer=Murata, Resistance=10k, Supplier Part Number 1=?
R79: "Res 470R 0603 1% 100mW 75V", Case Code (Imperial)=0603, Manufacturer=Uni-Royal, Power Rating=100mW, Resistance=470R, Resistance Tolerance=1%, Supplier Part Number 1=?
R80 R81 R82 R83 R84 R85 R86 R87 R88 R89 R90 R91 R92: "Res 1k 0603 1% 100mW 75V", Case Code (Imperial)=0603, Manufacturer=Uni-Royal, Power Rating=100mW, Resistance=1k, Resistance Tolerance=1%, Supplier Part Number 1=?
R103 R104: "Res 86k6 0603 1% 100mW 75V", Case Code (Imperial)=0603, Manufacturer=Uni-Royal, Power Rating=100mW, Resistance=86k6, Resistance Tolerance=1%, Supplier Part Number 1=?
X1: "XT30 Female THT Right-angle", Manufacturer="Changzhou Amass Elec"
X2: "JST XH 1x2 2.50mmP THT Right-angle", Manufacturer=JST
X4: "FPC connector 16p 1.0mmP SMD Right-angle", Manufacturer=XUNPU
X5 X6: "Standoff M3x6x6 Mechanical Male-Female", Manufacturer="Wurth Elektronik", Supplier Part Number 1=710-971060324
X7: "Female header 2x5 1.27mmP SMD Vertical", Manufacturer=HCTL
X8: "JTAG Cortex MCU Debug connector 2x5P 1.27mmP THT Right-angle", Manufacturer=Samtec
X10: "Pin header 1x3 2.54mmP THT Right-angle", Manufacturer=XFCN
X11 X12 X13 X14 X15 X16: "Female header 1x2 1.27mm THT Vertical", Manufacturer=hanxia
